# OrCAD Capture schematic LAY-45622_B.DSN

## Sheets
1 PAGE1: size A3; title: DK6 V3; rev: 1; note: CARRIER BOARD
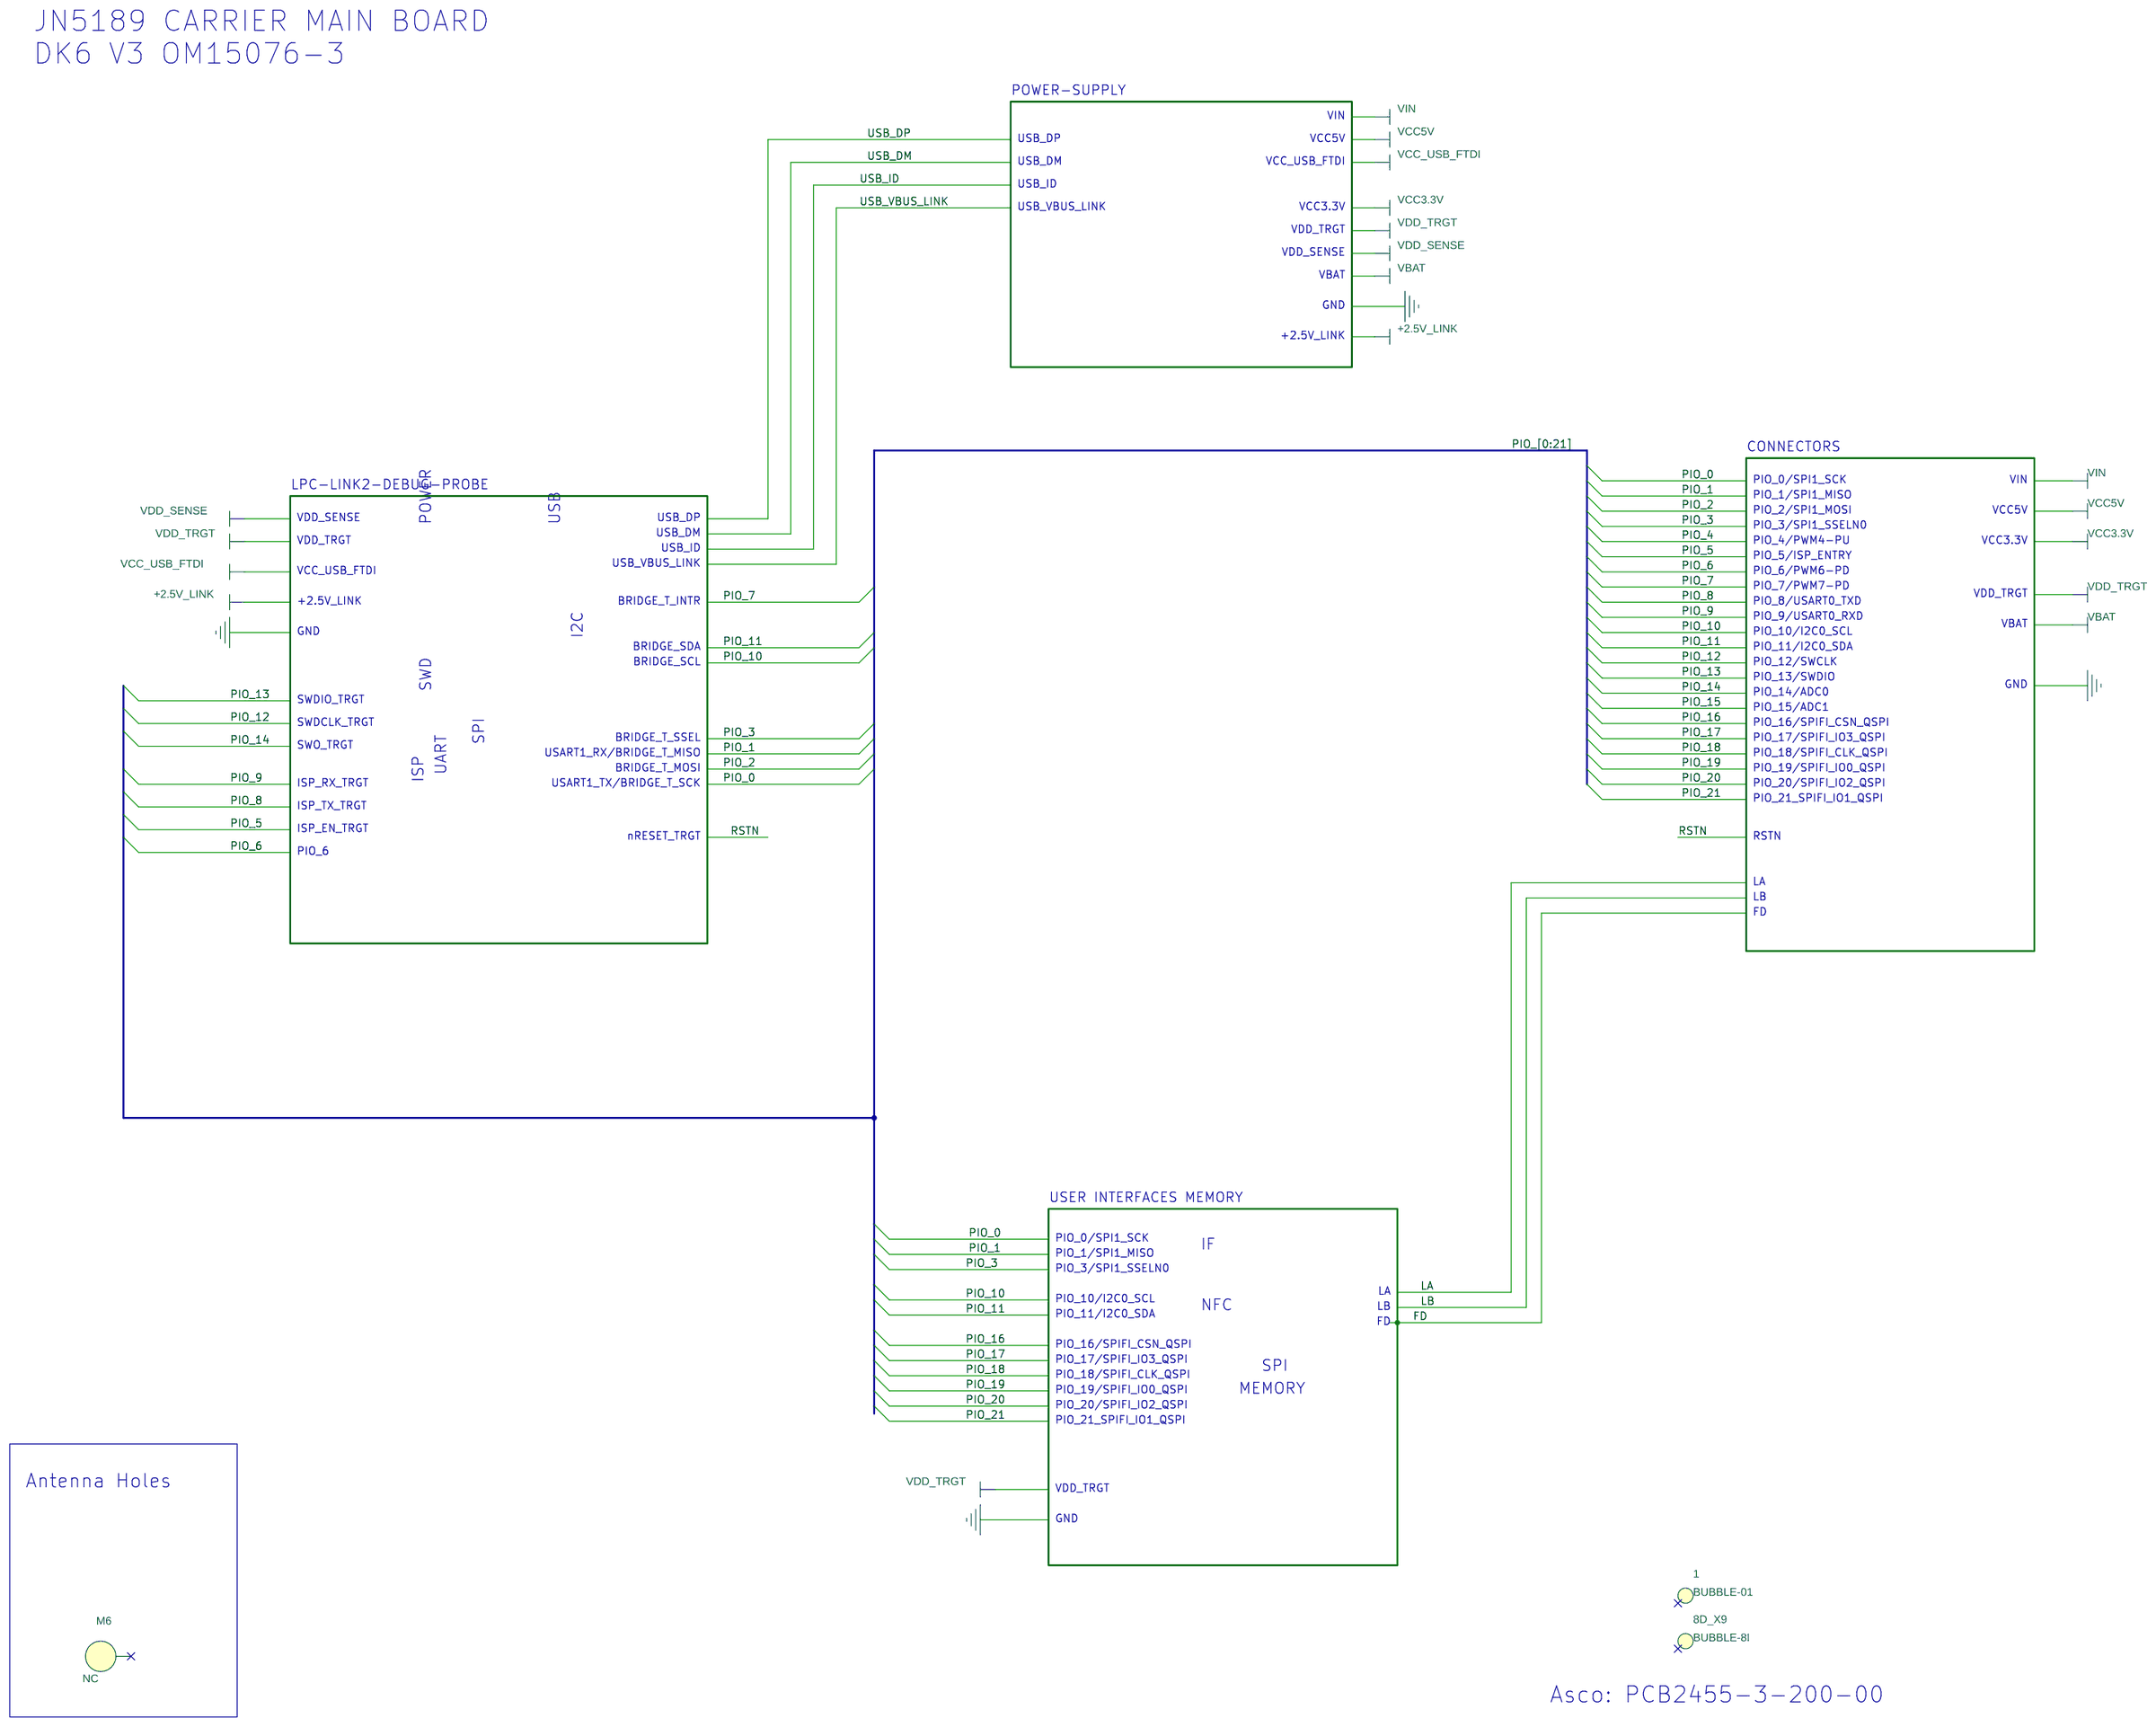
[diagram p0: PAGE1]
2 PAGE1 (2): size A3; title: LPC-LINK2-DEBUG-PROBE 1/3; block LPC-LINK2-DEBUG-PROBE
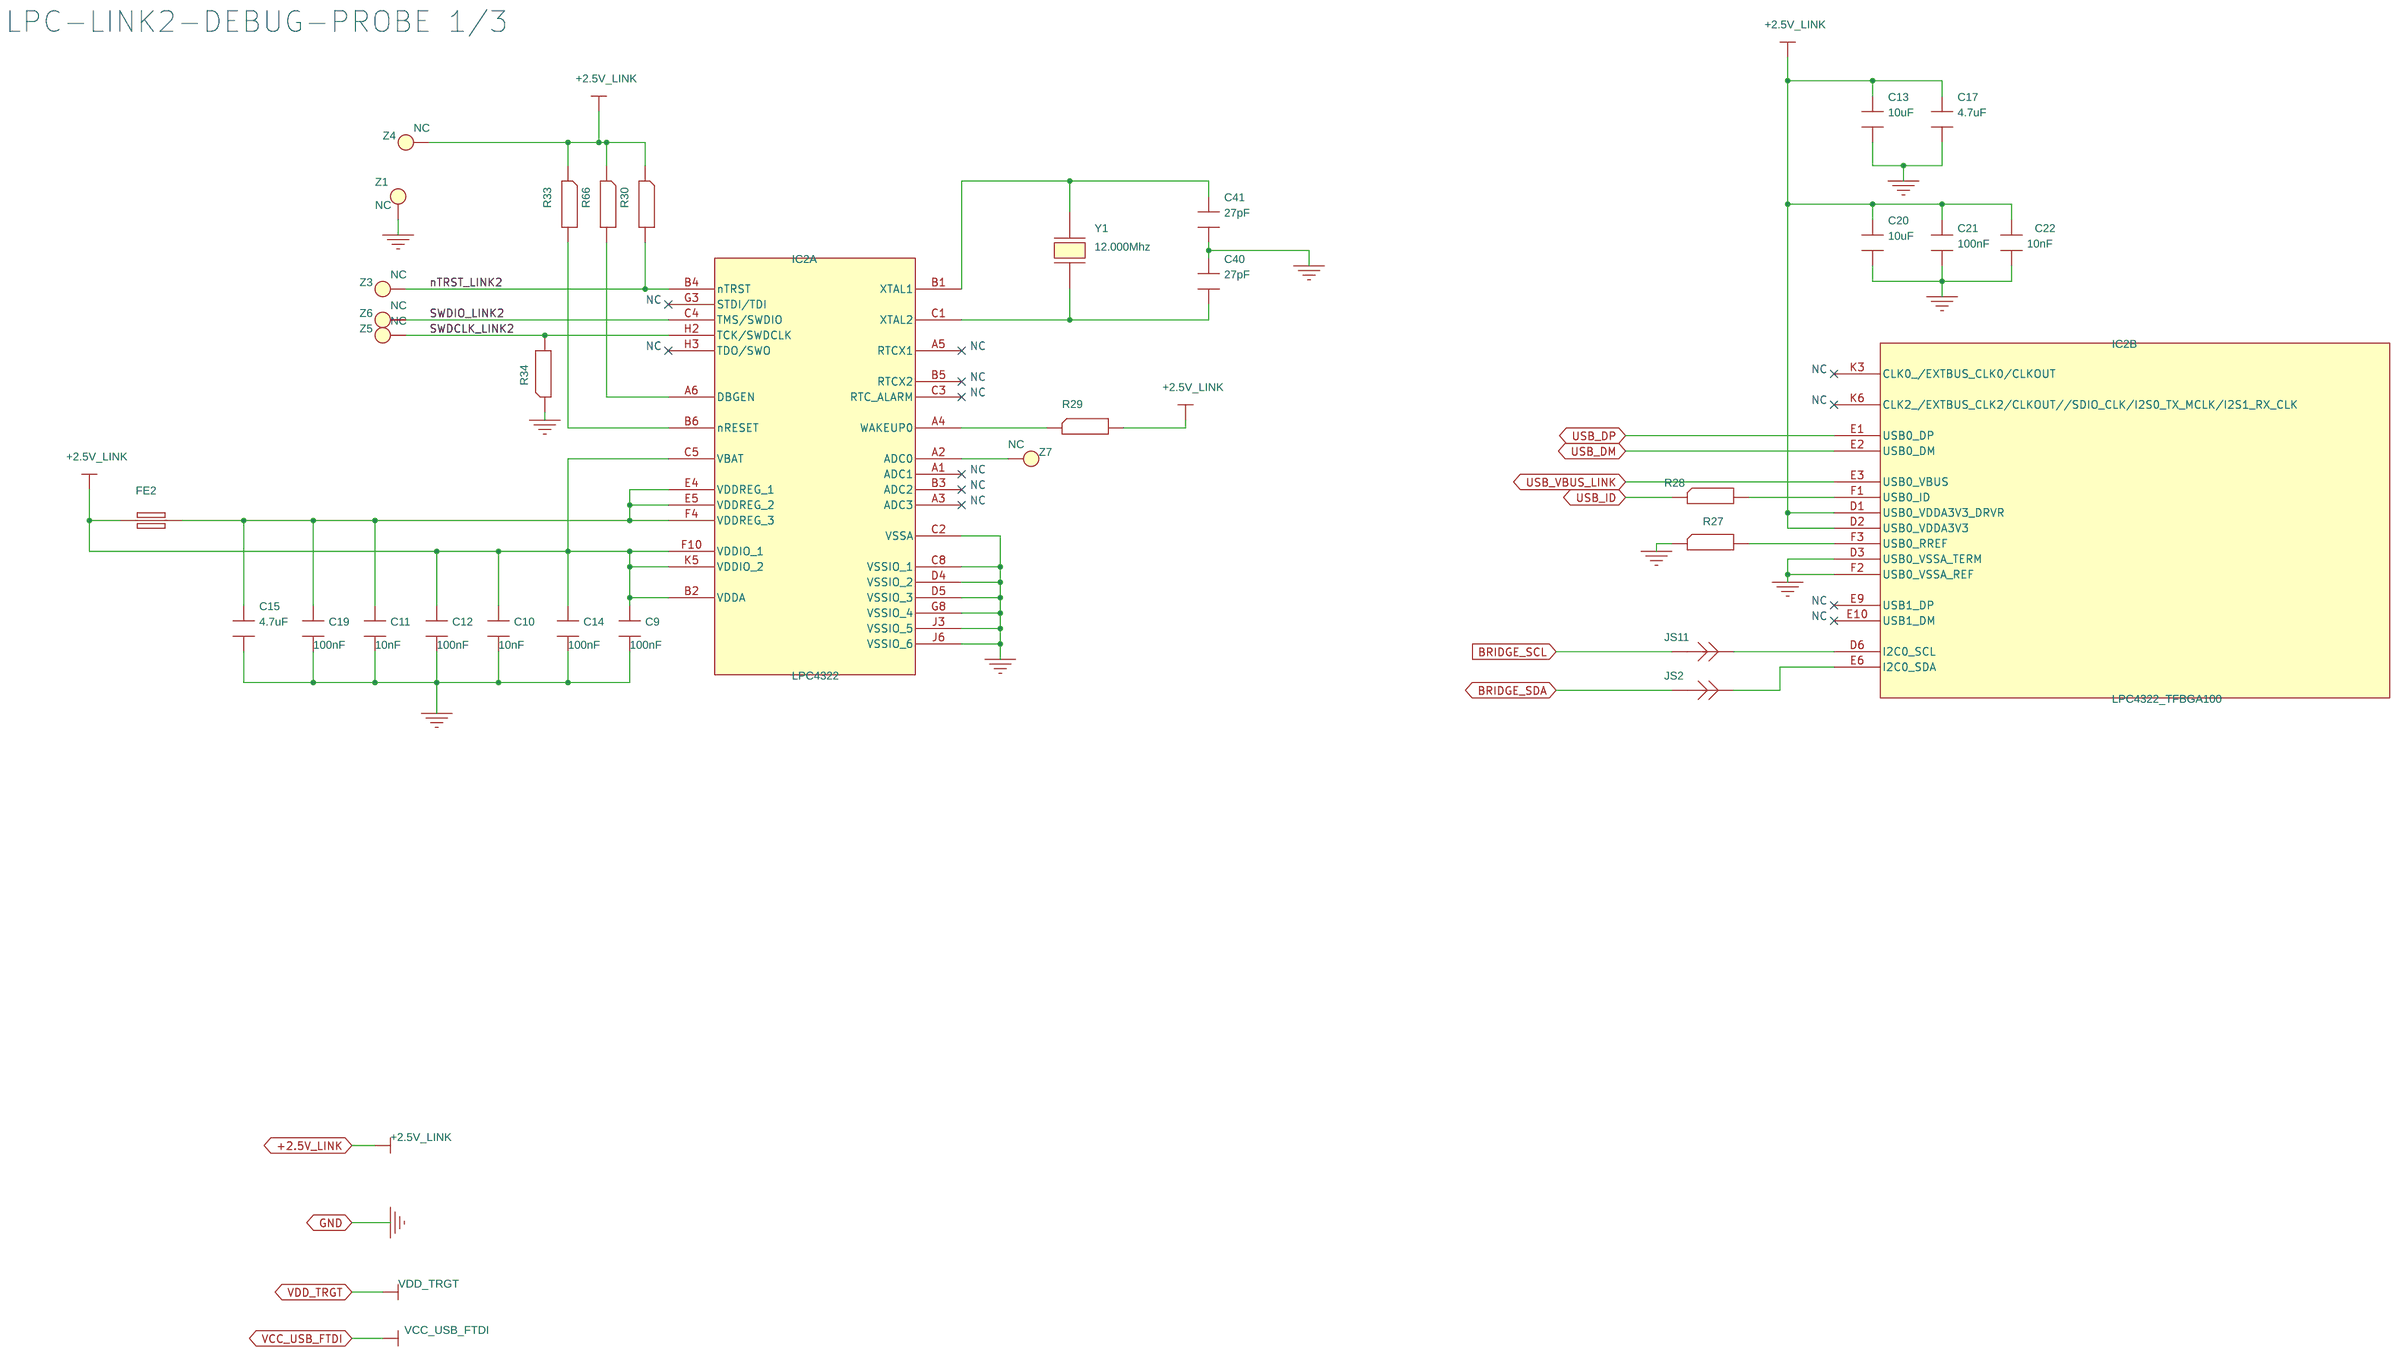
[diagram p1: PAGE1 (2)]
3 PAGE2: size A3; title: LPC-LINK2-DEBUG-PROBE 2/3; block LPC-LINK2-DEBUG-PROBE
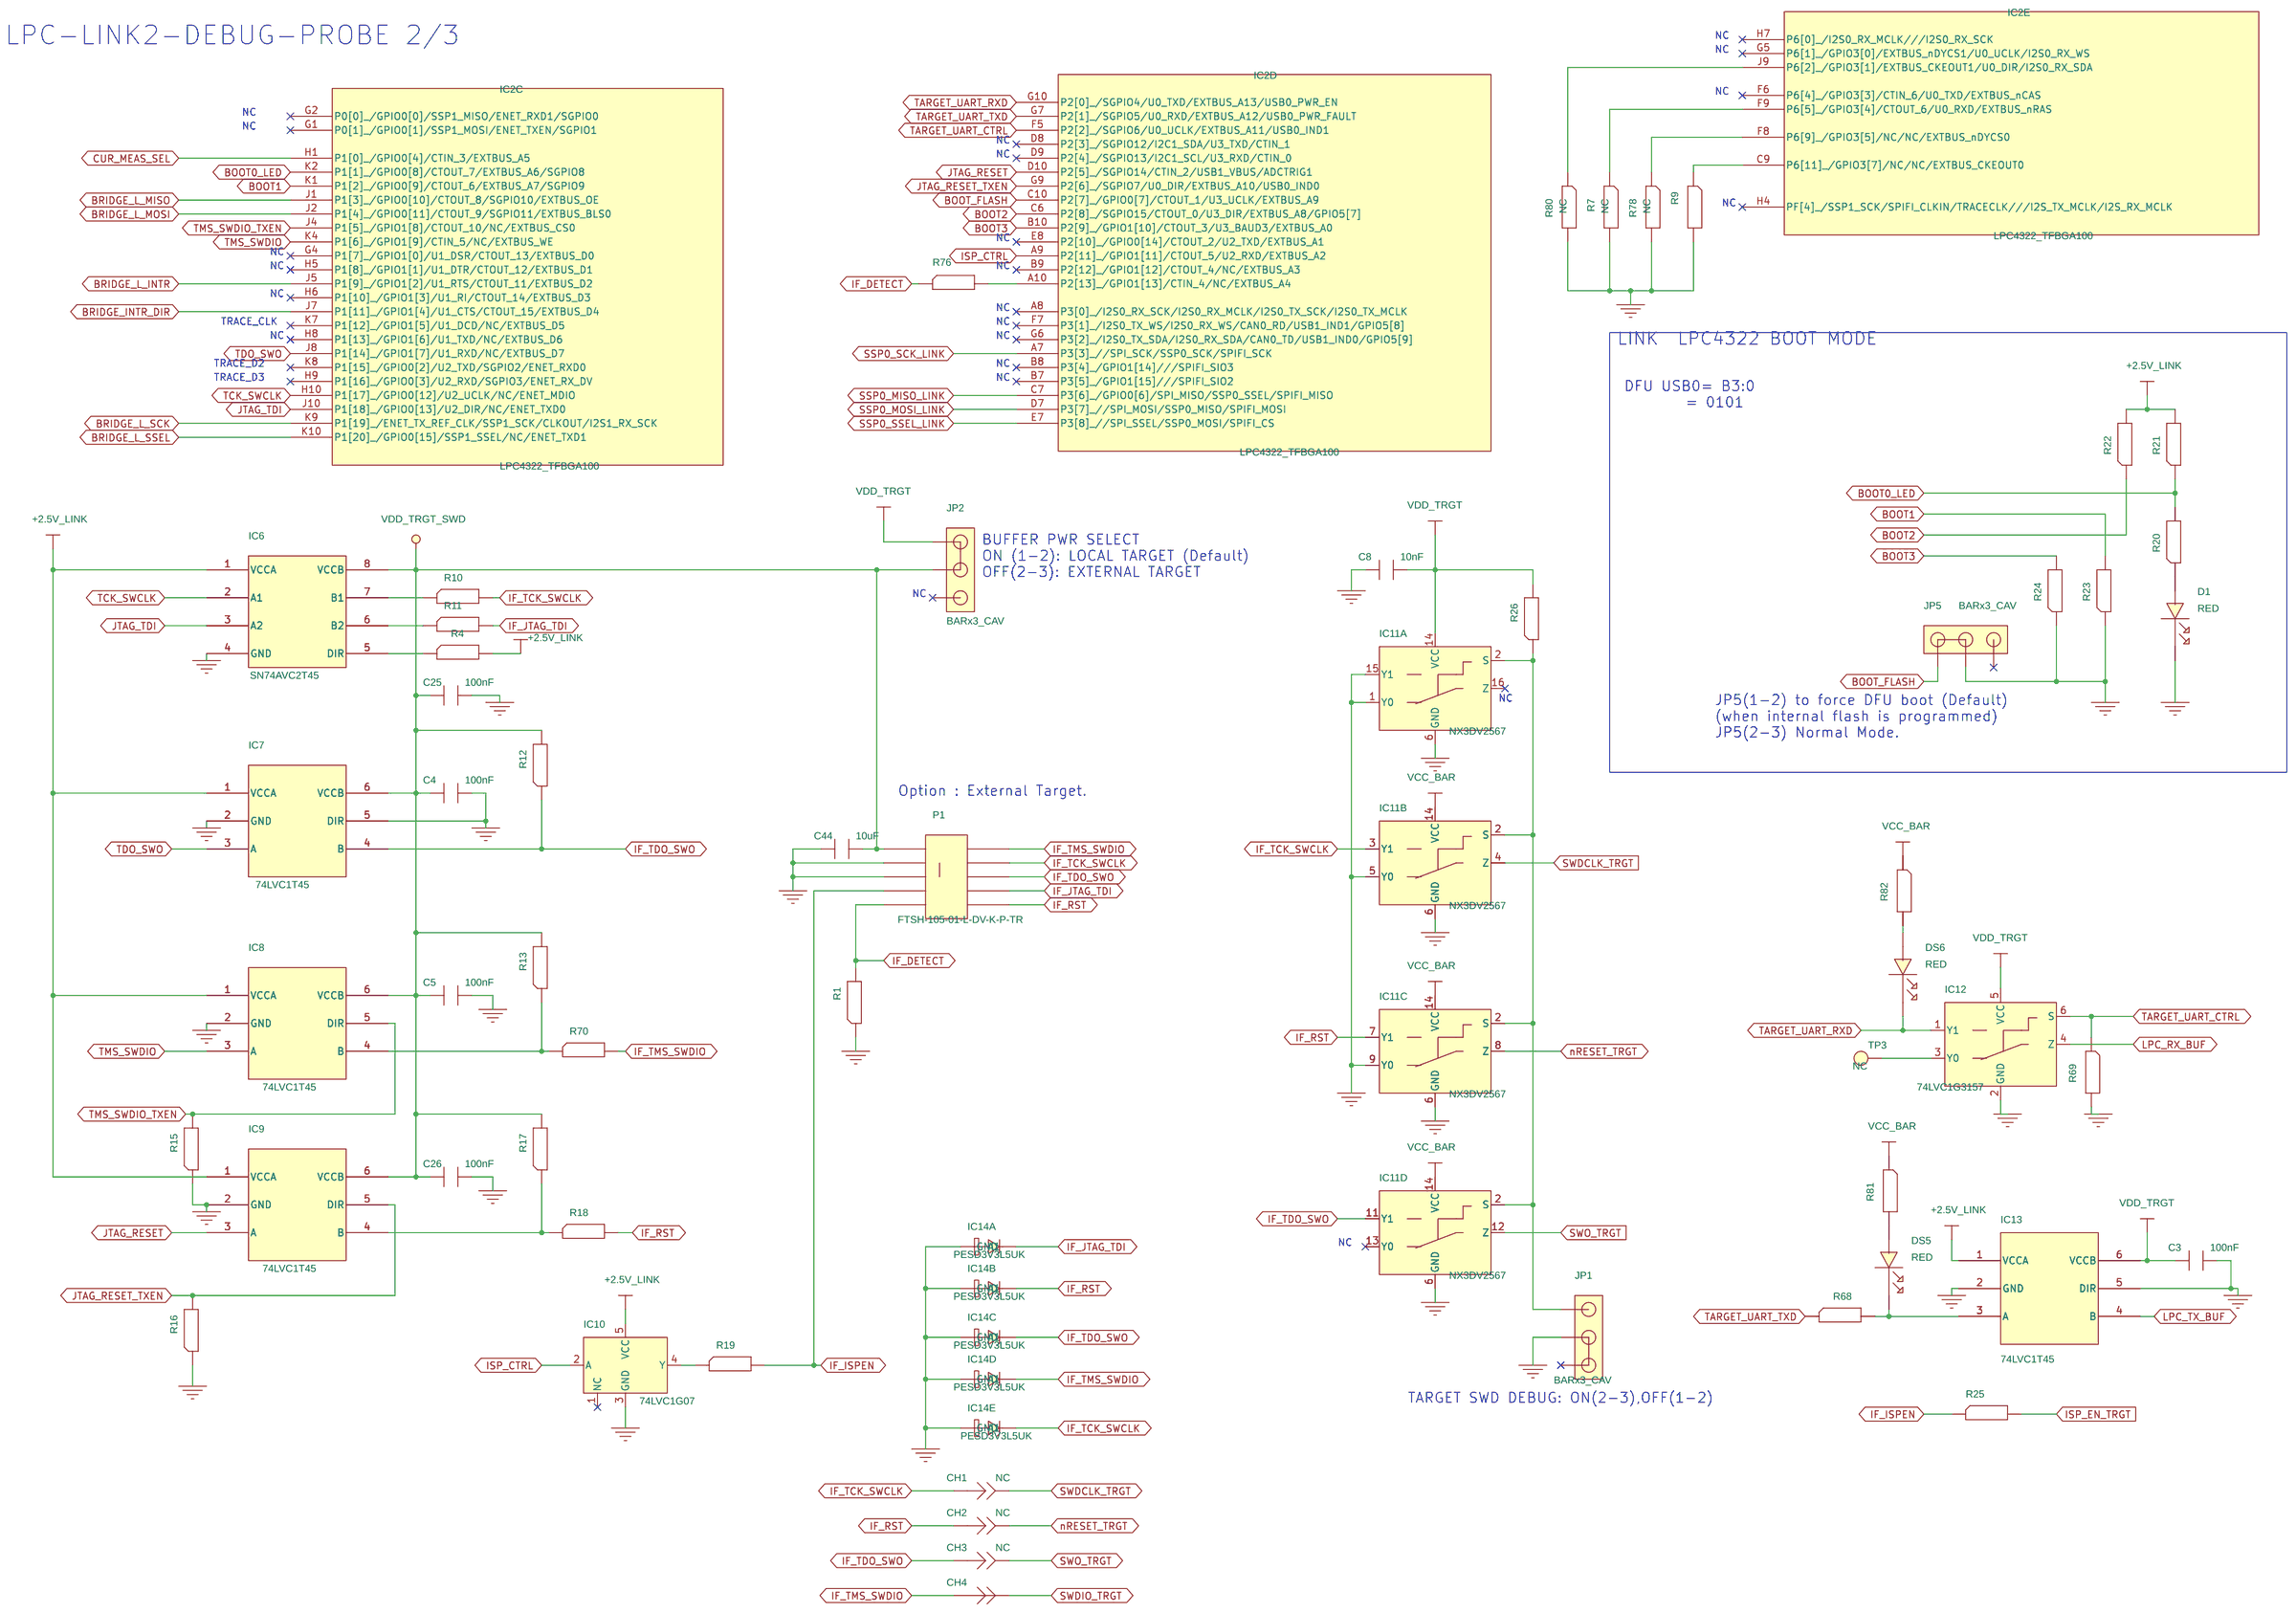
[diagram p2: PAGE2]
4 PAGE3: size A3; title: LPC-LINK2-DEBUG-PROBE 3/3; block LPC-LINK2-DEBUG-PROBE
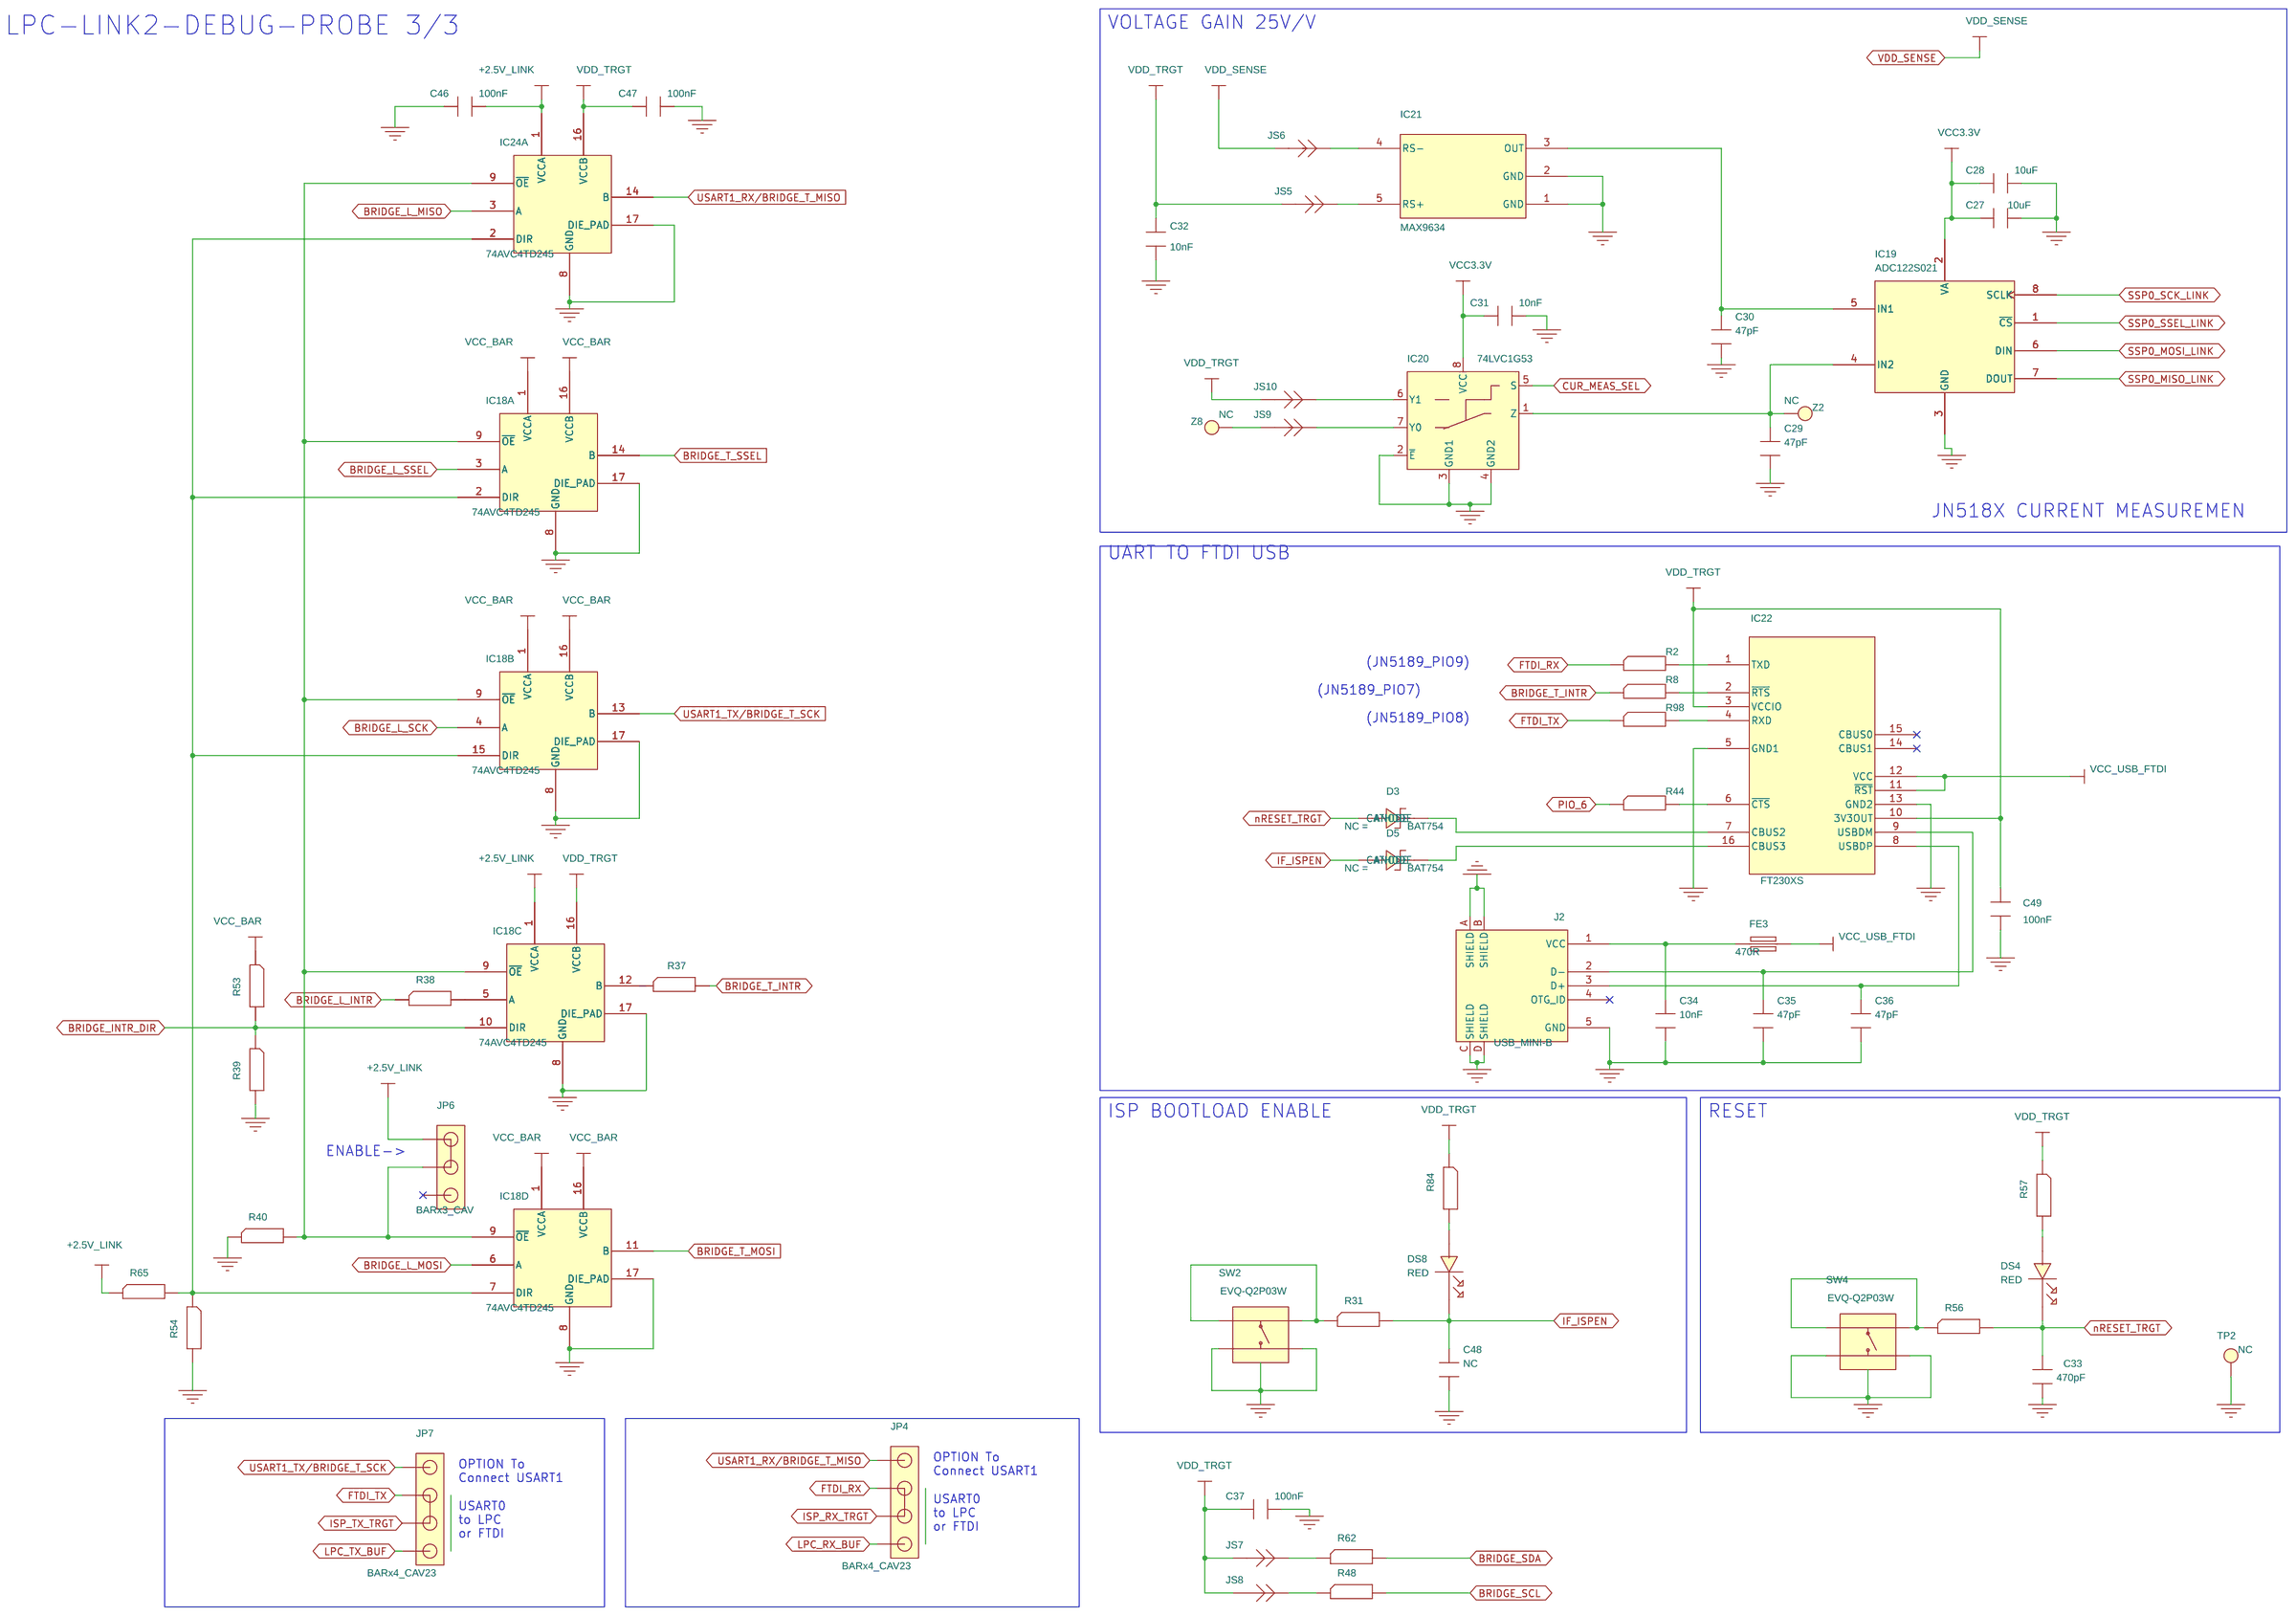
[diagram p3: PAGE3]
5 ALIM: size A3; title: POWER SUPPLY; block POWER-SUPPLY
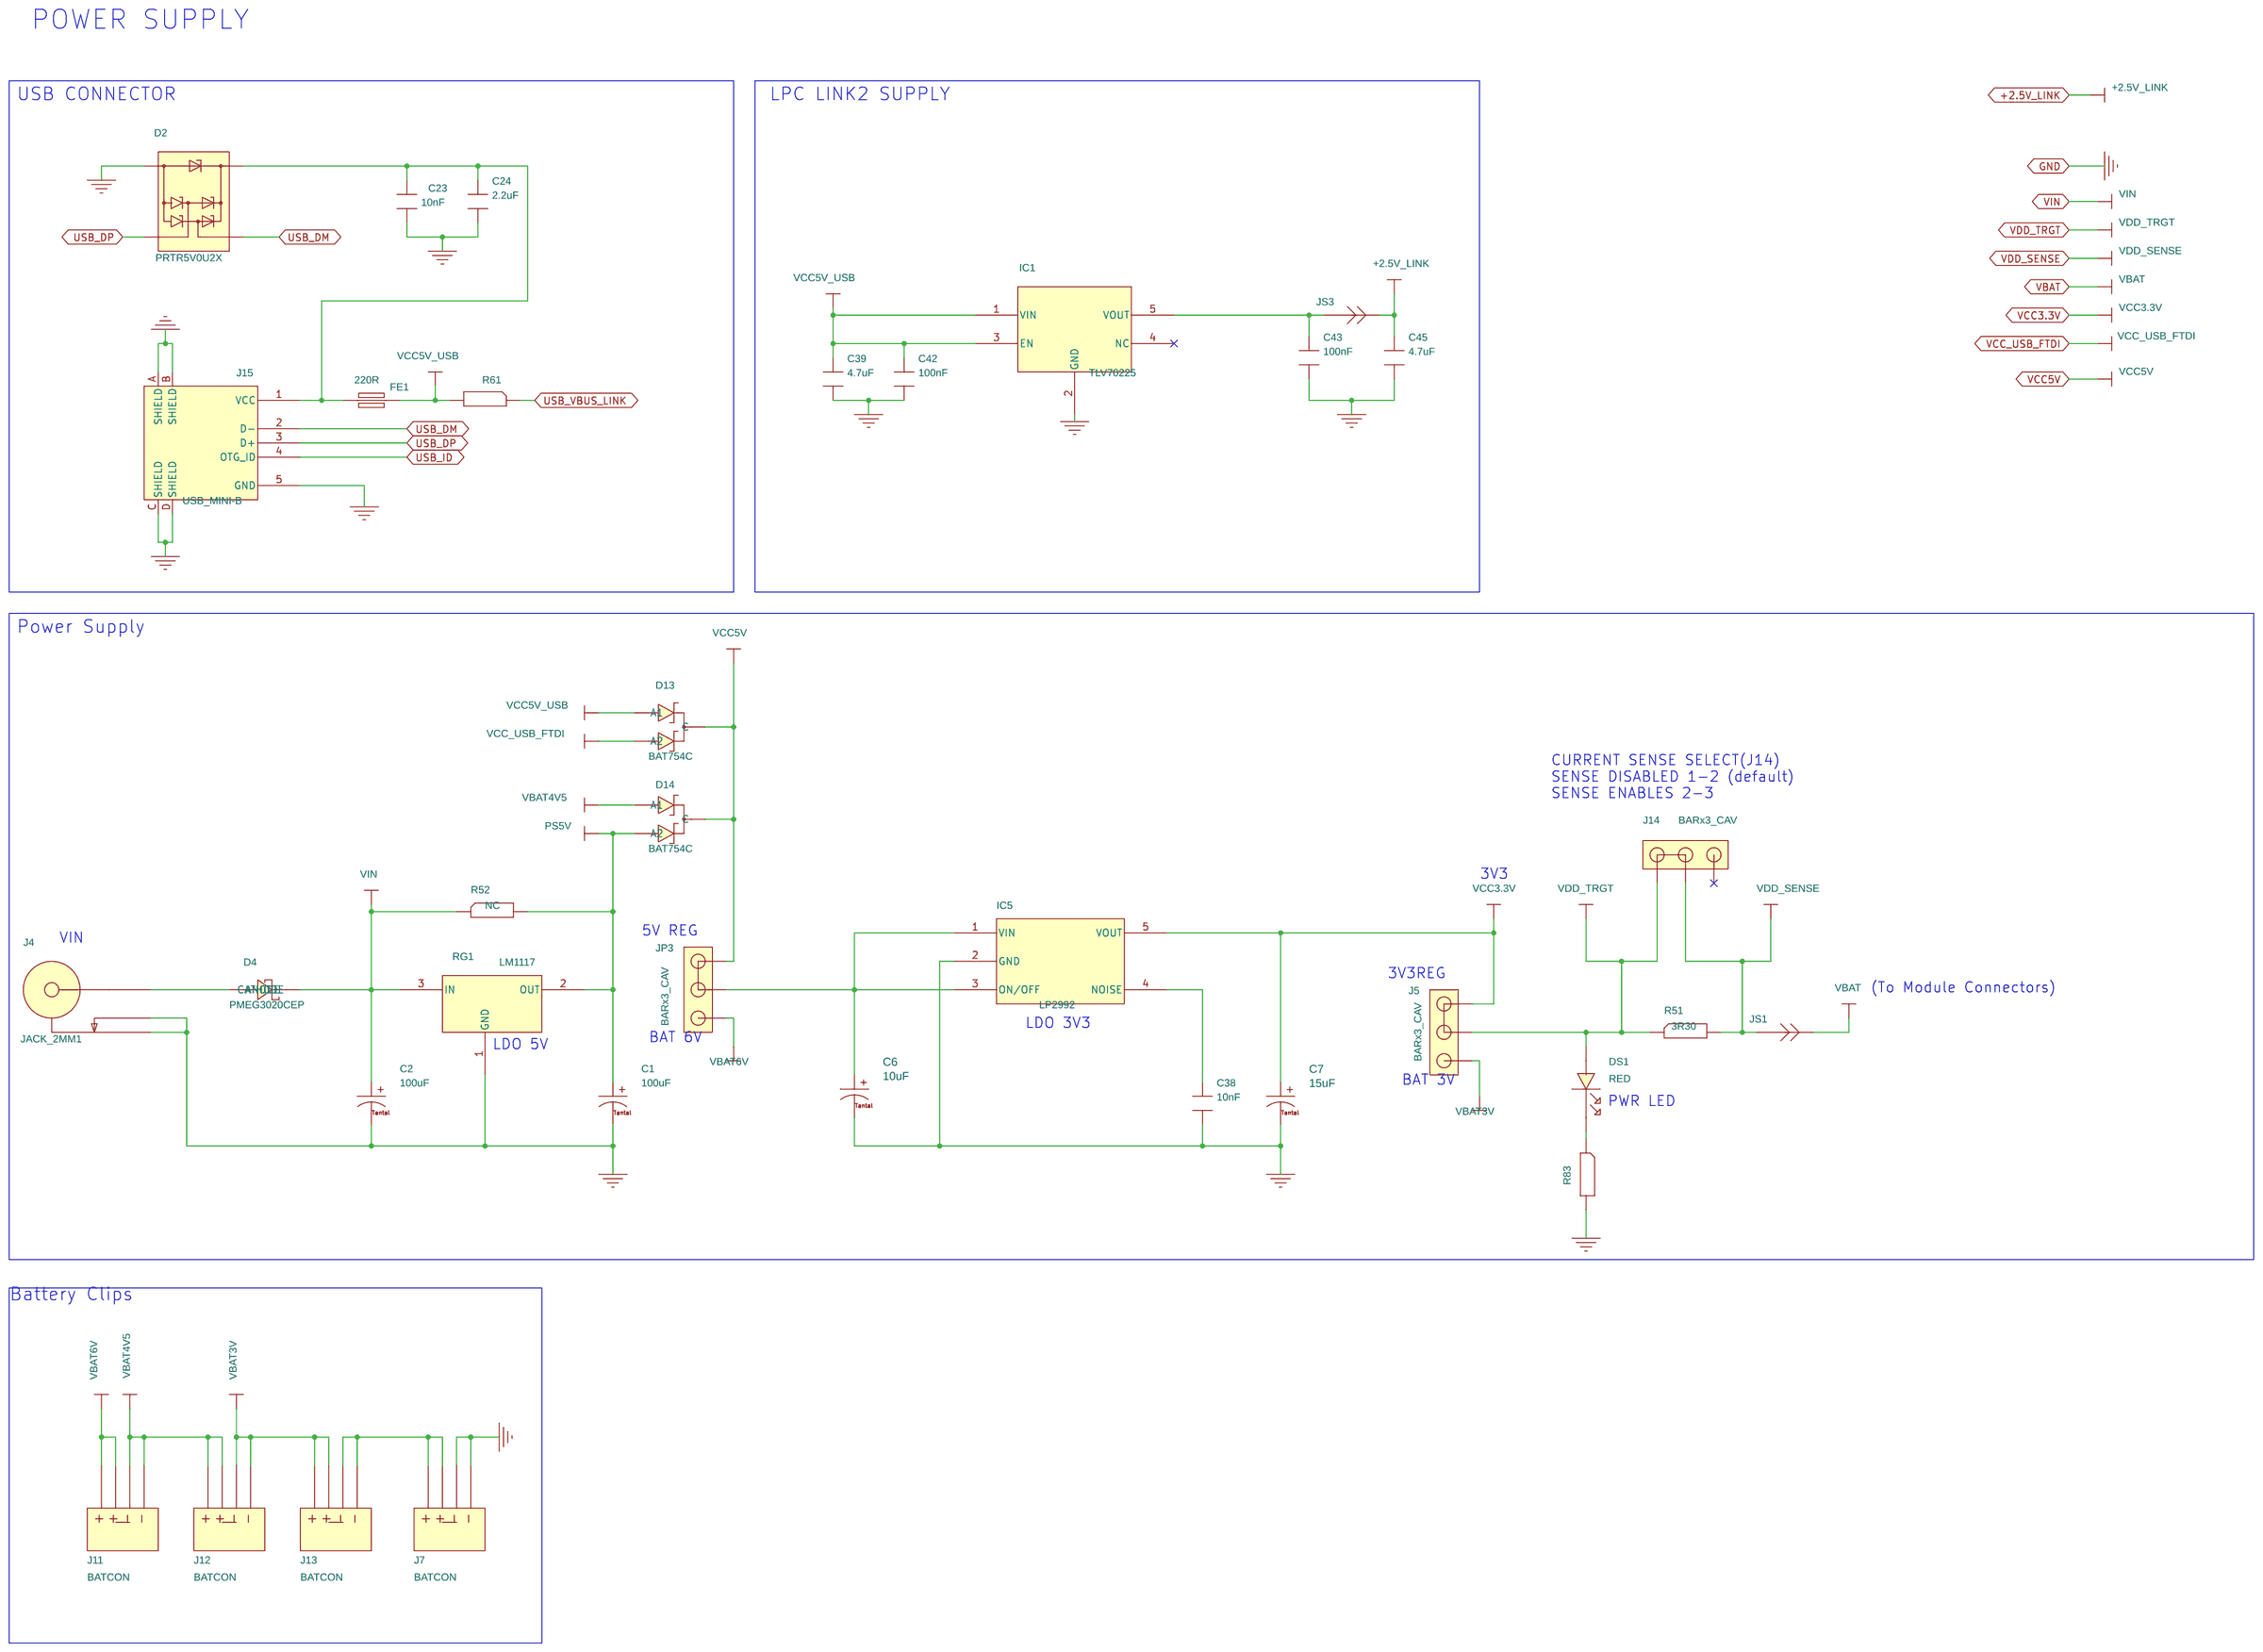
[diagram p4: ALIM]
6 PAGE1 (3): size A3; title: USER INTERFACES MEMORY; block USER INTERFACES MEMORY
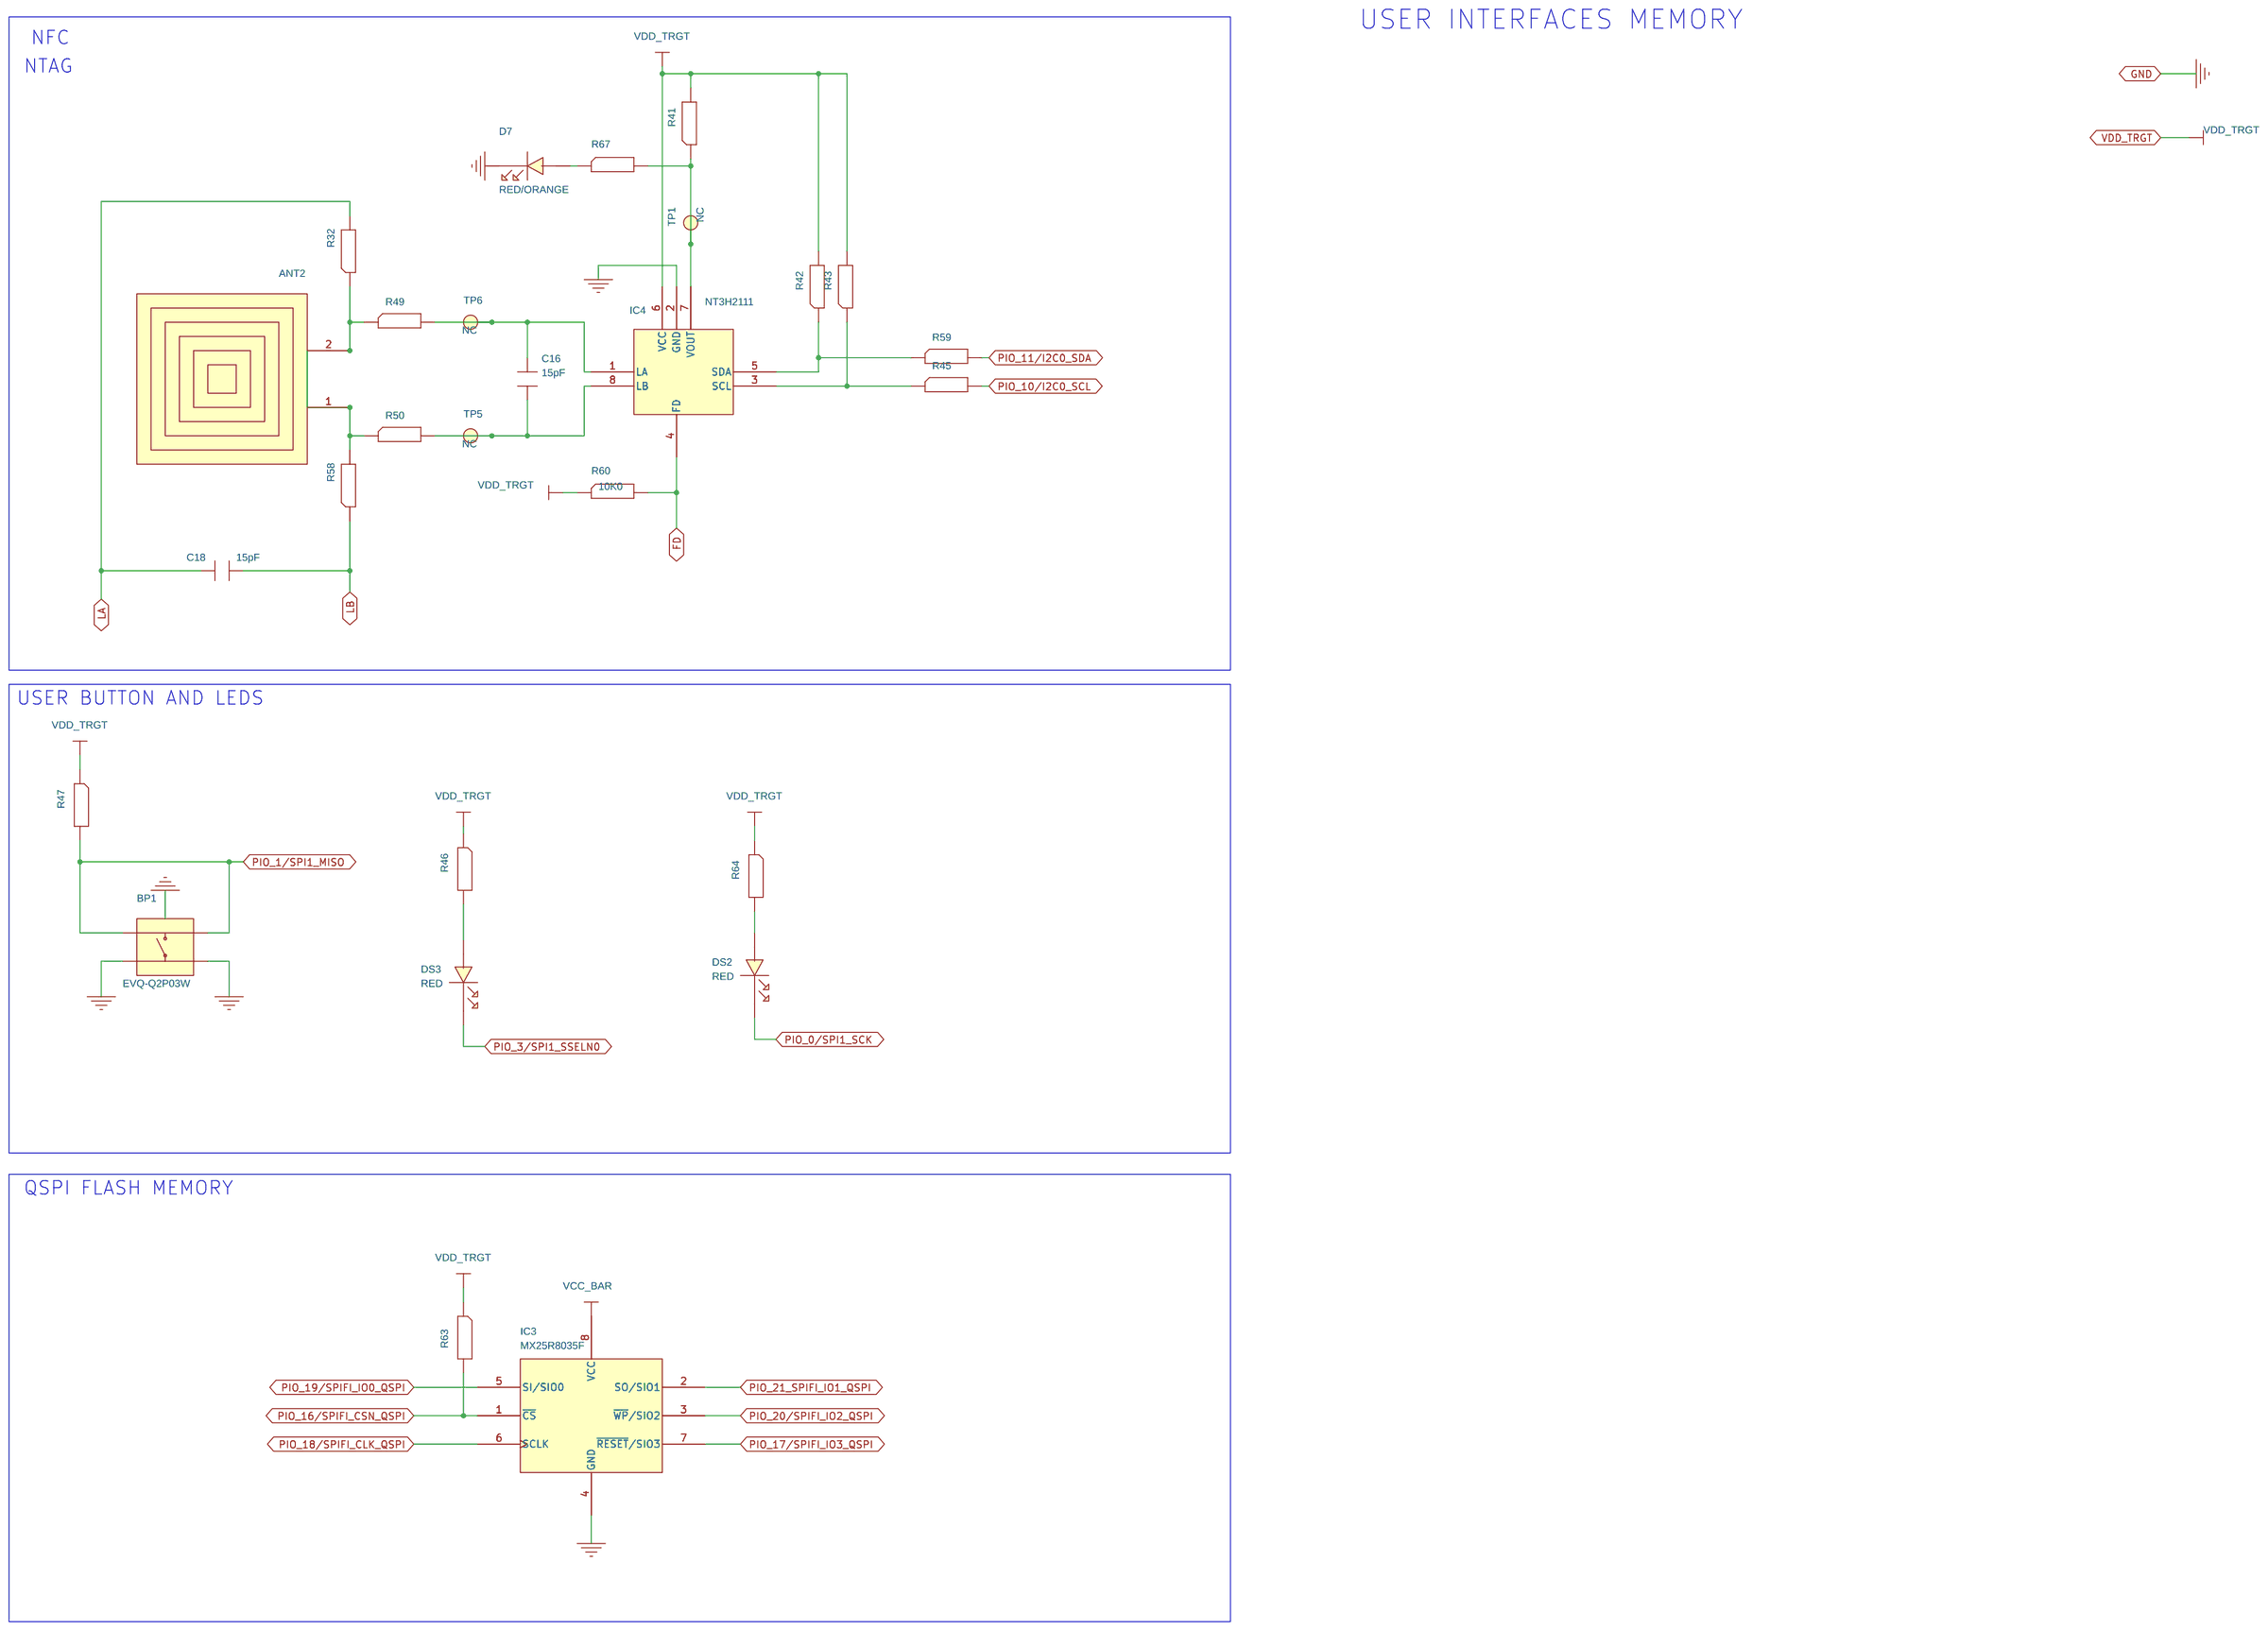
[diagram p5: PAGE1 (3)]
7 PAGE1 (4): size A3; title: CONNECTORS; block CONNECTORS
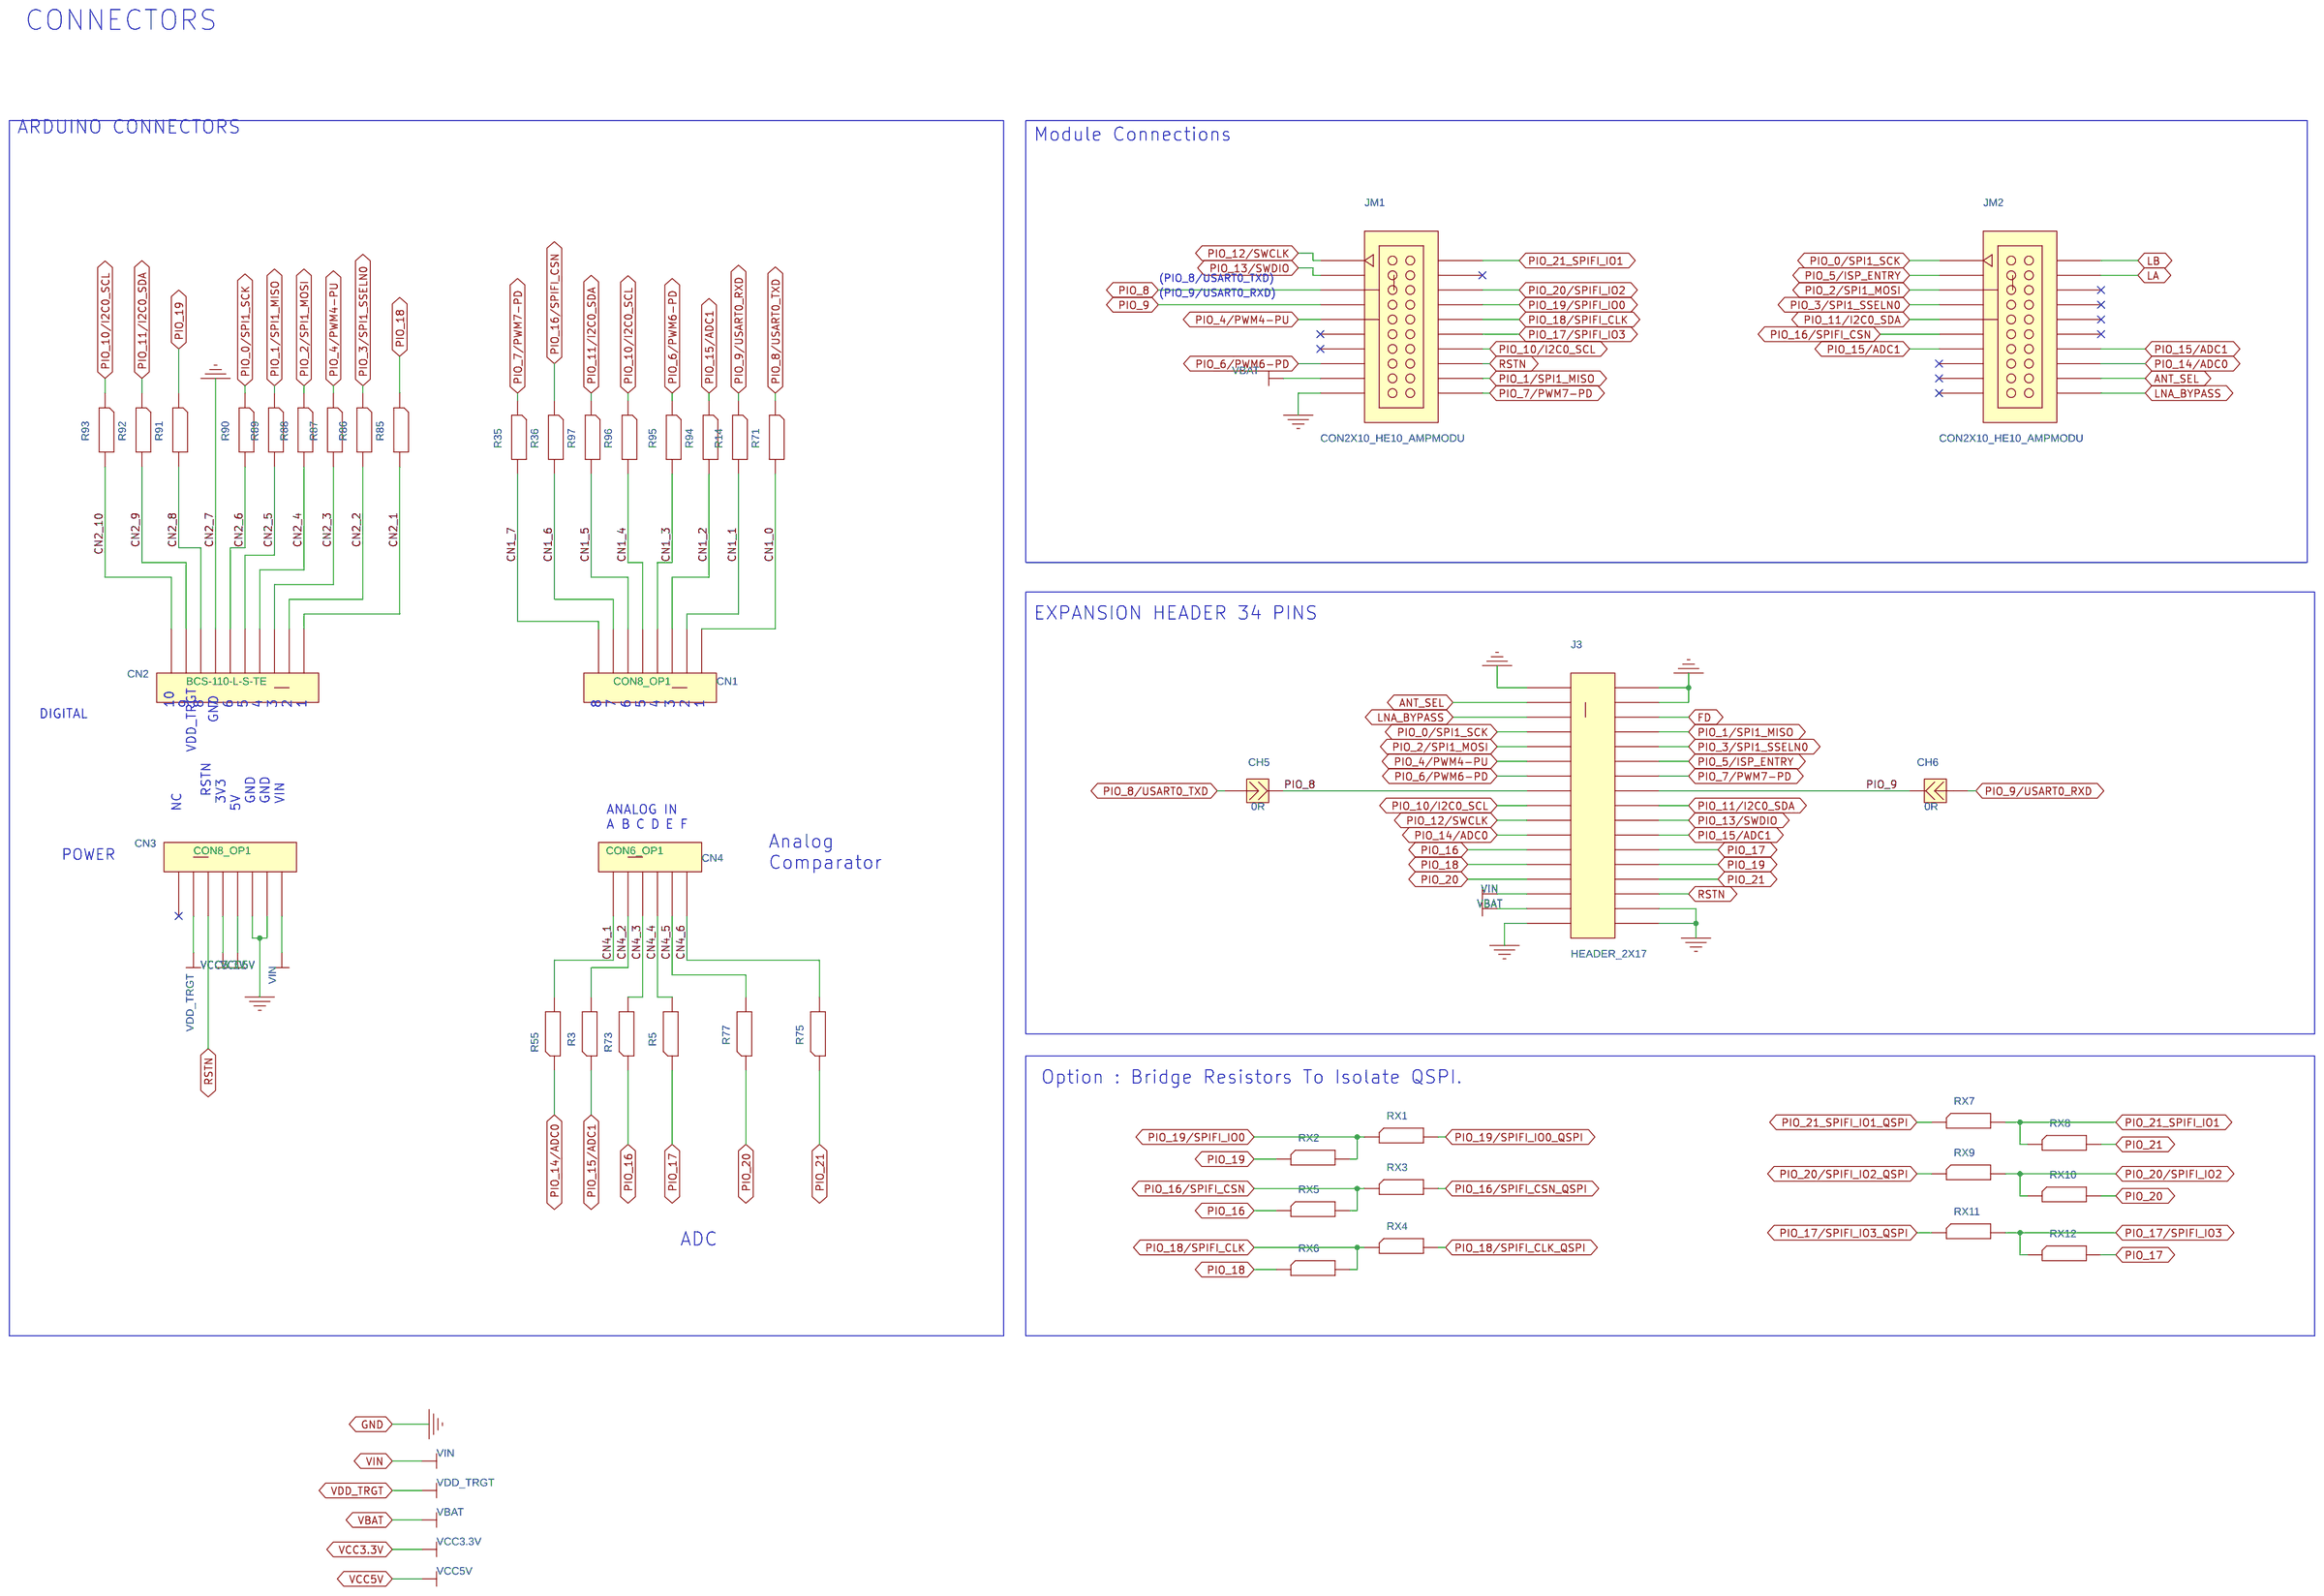
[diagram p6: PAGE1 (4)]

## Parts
sheet ALIM
C1  100uF  [7343-43_ipcb]
C2  100uF  [7343-43_ipcb]
C6  10uF  [TAJ_A]
C7  15uF  [TAJ_A]
C23  10nF  [C0402]
C24  2.2uF  [C0402]
C38  10nF  [C0402]
C39  4.7uF  [C0402]
C42  100nF  [C0402]
C43  100nF  [C0402]
C45  4.7uF  [C0402]
D2  PRTR5V0U2X  [SOT143B]
D4  PMEG3020CEP  [SOD128_A1_K2]
D13  BAT754C  [SOT23]
D14  BAT754C  [SOT23]
DS1  RED  [LED_0603_A_K]
FE1  220R  [blm18]
IC1  TLV70225  [SOT23_5_095]
IC5  LP2992  [SOT23_5_095]
J4  JACK_2MM1  [jack2_1_smt]
J5  BARx3_CAV  [bar_3pts_2mm00_cav12]
J7  BATCON  [BATCON_SMD_2CLIPS_AAA]
J11  BATCON  [BATCON_SMD_2CLIPS_AAA]
J12  BATCON  [BATCON_SMD_2CLIPS_AAA]
J13  BATCON  [BATCON_SMD_2CLIPS_AAA]
J14  BARx3_CAV  [bar_3pts_2mm00_cav12]
J15  USB_MINI-B  [usb_mini-b]
JP3  BARx3_CAV  [bar_3pts_2mm00_cav12]
JS1  NC  [CHEVRON_0603_F_COPPER]
JS3  NC  [CHEVRON_0603_F_COPPER]
R51  3R30  [R0402]
R52  NC  [R0402]
R61  270R  [R0402]
R83  680R  [R0402]
RG1  LM1117  [DPAK4_APPS]
sheet PAGE1 (2)
C9  100nF  [C0402]
C10  10nF  [C0402]
C11  10nF  [C0402]
C12  100nF  [C0402]
C13  10uF  [C0402]
C14  100nF  [C0402]
C15  4.7uF  [C0402]
C17  4.7uF  [C0402]
C19  100nF  [C0402]
C20  10uF  [C0402]
C21  100nF  [C0402]
C22  10nF  [C0402]
C40  27pF  [C0402]
C41  27pF  [C0402]
FE2  470R  [blm18]
IC2  LPC4322  [BGA100_080_SQ9]  (sections A,B,C,D,E)
JS2  NC  [CHEVRON_0603_F_COPPER]
JS11  NC  [CHEVRON_0603_F_COPPER]
R27  12K0  [R0402]
R28  0R  [R0402]
R29  100K  [R0402]
R30  12K0  [R0402]
R33  12K0  [R0402]
R34  2K20  [R0402]
R66  12K0  [R0402]
Y1  12.000Mhz  [HC49US_AT49]
Z1  NC  [VIA_0MM9]
Z3  NC  [VIA_0MM9]
Z4  NC  [VIA_0MM9]
Z5  NC  [VIA_0MM9]
Z6  NC  [VIA_0MM9]
Z7  NC  [VIA_0MM9]
sheet PAGE1 (3)
ANT2  NC  [ANT_6T_40MM5x24MM5]
BP1  EVQ-Q2P03W  [BP_EVQQ2]
C16  15pF  [C0402]
C18  15pF  [C0402]
D7  RED/ORANGE  [LED_0603_A_K]
DS2  RED  [LED_0603_A_K]
DS3  RED  [LED_0603_A_K]
IC3  MX25R8035F  [SOP8_127_200]
IC4  NT3H2111  [sot902-3]
R32  0R  [R0402]
R41  NC  [R0402]
R42  4K7  [R0402]
R43  4K7  [R0402]
R45  NC  [R0402]
R46  2K20  [R0402]
R47  2K20  [R0402]
R49  NC  [R0402]
R50  NC  [R0402]
R58  0R  [R0402]
R59  NC  [R0402]
R60  10K0  [R0402]
R63  100K  [R0402]
R64  2K20  [R0402]
R67  680R  [R0402]
TP1  NC  [plot050]
TP5  NC  [plot050]
TP6  NC  [plot050]
sheet PAGE1 (4)
CH5  0R  [CHEVRON_0603_F]
CH6  0R  [CHEVRON_0603_F]
CN1  CON8_OP1  [SIP-8P]
CN2  BCS-110-L-S-TE  [SIP-10P]
CN3  CON8_OP1  [SIP-8P]
CN4  CON6_OP1  [SIP-6P]
J3  HEADER_2X17  [header34_2x17_254]
JM1  CON2X10_HE10_AMPMODU  [AMPMODU_REC20_NOHOLES]
JM2  CON2X10_HE10_AMPMODU  [AMPMODU_REC20_NOHOLES]
R3  0R  [R0402]
R5  0R  [R0402]
R14  0R  [R0402]
R35  0R  [R0402]
R36  0R  [R0402]
R55  0R  [R0402]
R71  0R  [R0402]
R73  0R  [R0402]
R75  0R  [R0402]
R77  0R  [R0402]
R85  0R  [R0402]
R86  0R  [R0402]
R87  0R  [R0402]
R88  0R  [R0402]
R89  0R  [R0402]
R90  0R  [R0402]
R91  0R  [R0402]
R92  0R  [R0402]
R93  0R  [R0402]
R94  0R  [R0402]
R95  0R  [R0402]
R96  0R  [R0402]
R97  0R  [R0402]
RX1  0R  [R0402]
RX2  0R  [R0402]
RX3  0R  [R0402]
RX4  0R  [R0402]
RX5  0R  [R0402]
RX6  0R  [R0402]
RX7  0R  [R0402]
RX8  0R  [R0402]
RX9  0R  [R0402]
RX10  0R  [R0402]
RX11  0R  [R0402]
RX12  0R  [R0402]
sheet PAGE1
1  BUBBLE-01  [BUBBLE_DIAM8]
8D_X9  BUBBLE-8I  [BUBBLE_DIAM8]
M6  NC  [tp2-ha_apps_zi16]
sheet PAGE2
C3  100nF  [C0402]
C4  100nF  [C0402]
C5  100nF  [C0402]
C8  10nF  [C0402]
C25  100nF  [C0402]
C26  100nF  [C0402]
C44  10uF  [C0402]
CH1  NC  [CHEVRON_0603_O]
CH2  NC  [CHEVRON_0603_O]
CH3  NC  [CHEVRON_0603_O]
CH4  NC  [CHEVRON_0603_F_COPPER]
D1  RED  [LED_0603_A_K]
DS5  RED  [LED_0603_A_K]
DS6  RED  [LED_0603_A_K]
IC6  SN74AVC2T45  [MSOP8_065L]
IC7  74LVC1T45  [SOT-363_SC-88]
IC8  74LVC1T45  [SOT-363_SC-88]
IC9  74LVC1T45  [SOT-363_SC-88]
IC10  74LVC1G07  [SOT353_065]
IC11  NX3DV2567  [SOT1161-1_XQFN16]  (sections A,B,C,D)
IC12  74LVC1G3157  [SOT-363_SC-88]
IC13  74LVC1T45  [SOT-363_SC-88]
IC14  PESD3V3L5UK  [SOT891_XSON6]  (sections A,B,C,D,E)
JP1  BARx3_CAV  [bar_3pts_2mm00_cav23]
JP2  BARx3_CAV  [bar_3pts_2mm00_cav12]
JP5  BARx3_CAV  [bar_3pts_2mm00_cav12]
P1  FTSH-105-01-L-DV-K-P-TR  [CON_SAMTEC_FTSH_105_01_L_DV_K]
R1  0R  [R0402]
R4  100K  [R0402]
R7  NC  [R0402]
R9  2K20  [R0402]
R10  100R  [R0402]
R11  100R  [R0402]
R12  100K  [R0402]
R13  100K  [R0402]
R15  2K20  [R0402]
R16  2K20  [R0402]
R17  100K  [R0402]
R18  100R  [R0402]
R19  100R  [R0402]
R20  2K20  [R0402]
R21  2K20  [R0402]
R22  2K20  [R0402]
R23  2K20  [R0402]
R24  2K20  [R0402]
R25  0R  [R0402]
R26  100K  [R0402]
R68  100R  [R0402]
R69  2K20  [R0402]
R70  100R  [R0402]
R76  1K50  [R0402]
R78  NC  [R0402]
R80  NC  [R0402]
R81  680R  [R0402]
R82  680R  [R0402]
TP3  NC  [plot050]
sheet PAGE3
C27  10uF  [C0402]
C28  10uF  [C0402]
C29  47pF  [C0402]
C30  47pF  [C0402]
C31  10nF  [C0402]
C32  10nF  [C0402]
C33  470pF  [C0402]
C34  10nF  [C0402]
C35  47pF  [C0402]
C36  47pF  [C0402]
C37  100nF  [C0402]
C46  100nF  [C0402]
C47  100nF  [C0402]
C48  NC  [C0402]
C49  100nF  [C0402]
D3  BAT754  [SOT23]
D5  BAT754  [SOT23]
DS4  RED  [LED_0603_A_K]
DS8  RED  [LED_0603_A_K]
FE3  470R  [blm18]
IC18  74AVC4TD245  [SOT763-1_DHVQFN20_050]  (sections A,B,C,D)
IC19  ADC122S021  [MSOP8_065L]
IC20  74LVC1G53  [SOT765-1_VSSOP8]
IC21  MAX9634  [SOT23_5_095]
IC22  FT230XS  [jedec_mo137_ab_ssop16]
IC24  74AVC4TD245  [SOT763-1_DHVQFN20_050]  (section A)
J2  USB_MINI-B  [usb_mini-b]
JP4  BARx4_CAV23  [bar_4pts_2mm00_cav23]
JP6  BARx3_CAV  [bar_3pts_2mm00_cav12]
JP7  BARx4_CAV23  [bar_4pts_2mm00_cav23]
JS5  NC  [CHEVRON_0603_F_COPPER]
JS6  NC  [CHEVRON_0603_F_COPPER]
JS7  NC  [CHEVRON_0603_F_COPPER]
JS8  NC  [CHEVRON_0603_F_COPPER]
JS9  NC  [CHEVRON_0603_F_COPPER]
JS10  NC  [CHEVRON_0603_F_COPPER]
R2  0R  [R0402]
R8  NC  [R0402]
R31  0R  [R0402]
R37  2K20  [R0402]
R38  2K20  [R0402]
R39  2K20  [R0402]
R40  2K20  [R0402]
R44  NC  [R0402]
R48  4K7  [R0402]
R53  NC  [R0402]
R54  NC  [R0402]
R56  0R  [R0402]
R57  2K20  [R0402]
R62  4K7  [R0402]
R65  100K  [R0402]
R84  2K20  [R0402]
R98  0R  [R0402]
SW2  EVQ-Q2P03W  [BP_EVQQ2]
SW4  EVQ-Q2P03W  [BP_EVQQ2]
TP2  NC  [plot10]
Z2  NC  [VIA_0MM9]
Z8  NC  [VIA_0MM9]

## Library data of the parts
C1 C2 = CAPA_TANTALE: Designation: Capacitor T521 100uF 20% 25V (Boitier X (7343-43)); MANUFACTURER_REFERENCE: KEMET (T521X107M025ATE060); Package: 7343-43; Part Number: 0-00-305210A; Part Type: Capacitor; Tension: 25V; Tol: 20%
C6 = CAPA_TANTALE: Designation: Capacitor TAJ 10uF 10% 10V (boitier_A); MANUFACTURER_REFERENCE: KEMET (T491A106K010AT); Package: TAJ_boitier_A; Part Number: 0-00-301422B; Part Type: Capacitor; Supplier: FARNELL; Tension: 10V; Tol: 10%
C7 = CAPA_TANTALE: Designation: Capacitor Tantal 15uF 20% 6.3V (Boitier A); Package: 3216-18; Part Number: 0-00-300746; Part Type: Capacitor; Tension: 6.3V; Tol: 20%
C8 C10 C11 C22 C23 C31 C32 C38 = CAPA: Alt_Symbols: 0402C; Designation: Capacitor 0402 10nF 10% 16V X7R (-55°C+125°C); Gamme: X7R; Package: 402; Part Number: 0-00-300071; Temp: (-55°C+125°C); Tension: 16V; Tol: 10%
C24 = CAPA: Alt_Symbols: 0402C; Designation: Capacitor 0402 2.2uF 20% 10V X5R (-55°C+85°C); Gamme: X5R; Package: 402; Part Number: 0-00-300104; Temp: (-55°C+85°C); Tension: 10V; Tol: 20%
C15 C17 C39 C45 = CAPA: Alt_Symbols: 0402C; Designation: Capacitor 0402 4.7uF 10% 10V X5R (-55°C+85°C); Gamme: X5R; Package: 402; Part Number: 0-00-300143; Tension: 10V; Tol: 10%
C3-C5 C9 C12 C14 C19 C21 C25 C26 C37 C42 C43 C46 C47 = CAPA: Alt_Symbols: 0402C; Designation: Capacitor 0402 100nF 10% 10V X5R (-55°C+85°C); Gamme: X5R; Package: 402; Part Number: 0-00-300052; Temp: (-55°C+85°C); Tension: 10V; Tol: 10%
D2 = PRTR5V0U2AX: Designation: Diode PRTR5V0U2AX (SOT-143B) - PRTR5V0U2AX  (-40°C to 85°C); Part Number: 0-00-402852; Part Type: DIODE; Temp: (-40°C to 85°C)
D4 = DIODE_SCHOTTKY: Designation: Diode Schoktty PMEG3020CEP (SOD-128); Manufacturer_reference: NXP (PMEG3020CEP,115); Package: SOD-128; Part Number: 0-00-401760; Part Type: DIODE
D13 D14 = DIODE2A1K_SCHOT: Designation: Diode Schoktty BAT754C (SOT23) - BAT754C; Part Number: 0-00-402573; Part Type: DIODE
D1 DS1-DS6 DS8 = LED: Designation: LED 0603 RED LS-Q976 (-30°C to 85°C); Manufacturer_reference: OSRAM (LS Q976); Package: 0603; Part Number: 0-00-001292; Supplier: RADIOSPARES; Temp: (-30°C to 85°C)
FE1 = FERRITE_2: Designation: Ferrite Bead (220R - 100MHz); Manufacturer_reference: MURATA (BLM18PG221SN1D); Package: BLM18; Part Number: 0-00-002187; Part Type: FERRITE
IC1 = TLV702_SOT: Designation: 2.5V Regulator TLV70225DBVR (SOT-23(5)) - (-40°C to +125°C); Manufacturer_reference: TEXAS INSTRUMENTS (TLV70225DBVR); Package: SOT-23; Part Number: 0-00-403918; Part Type: REGULATOR; Temp: (-40°C to +125°C)
IC5 = LP2992: Designation: 3.3V Regulator LP2992AIM5-3.3/NOPB (SOT-23(5)); Manufacturer_reference: TEXAS INSTRUMENTS (LP2992AIM5-3.3/NOPB); Package: SOT-23; Part Number: 0-00-401103; Part Type: REGULATOR
J4 = JACK2.1_H_NC4: Designation: Connector DC Power 2.1mm Socket SMT; Manufacturer_reference: LUMBERG (1613 14); Package: JACK; Part Number: 0-00-202647; Part Type: CONNECTOR
J5 J14 JP2 JP3 JP5 JP6 = bar_1x3_MD_CAV_1-2: Designation: Header Single Row 3Pts Straight 2mm00 + BUBBLE-8I; Manufacturer_reference: HARWIN (M22-2510305); Package: 2MM; Part Number: 0-00-200117_CAV_BLACK; Part Type: CON_2MM
J7 J11-J13 = BATCON: Designation: Connector - SMT Battery Clip AAA (x2); Manufacturer: Keystone; Package: CLIP_AAA; Part Type: CONNECTOR; Part number: 0-00-100190_x2; REF.Manufacturer: 55; manufacturer_reference: KEYSTONE (55), RAMSES S.A.S (55)
J2 J15 = USB_MINI-B: Designation: Mini-B USB connector (SMD); Manufacturer_reference: MOLEX (0675031020); Part Number: 0-00-202936; Part Type: USB
CH4 JS1-JS3 JS5-JS11 = Chevron_0603_f_cop: Designation: !!! Not Connected !!! (Copper Close By Default); PACKAGE: 603; Part Number: 0-00-3CHEVRON-F-COPPER; Part Type: CHEVRON
R51 = RES: Alt_Symbols: 0402R; Designation: Resistor 0402 3R30 1% 100ppm -; PACKAGE: 402; PPM: 100ppm; Part Number: 0-00-304913; TOL: 1%; Type: CMS
R7 R8 R41 R44 R45 R49 R50 R52-R54 R59 R78 R80 = RES: Designation: !!! NOT CONNECTED !!!; PACKAGE: 402; Part Number: 0-00-3NC_R0402
R61 = RES: Alt_Symbols: 0402R; Designation: Resistor 0402 270R 1% 100ppm -; PACKAGE: 402; PPM: 100ppm; Part Number: 0-00-302048; TOL: 1%; Type: CMS
R67 R81-R83 = RES: Designation: Resistor 0402 680R 1% 100ppm -; MANUFACTURER_REFERENCE: YAGEO (PHYCOMP) (RC0402FR-07680RL); PACKAGE: 402; PPM: 100ppm; Part Number: 0-00-302143A; TOL: 1%; Type: CMS
RG1 = LM1117: Designation: Integrated Circuit LM1117DT-5.0/NOPB (TO-252); Manufacturer_reference: TEXAS INSTRUMENTS (LM1117DT-5.0/NOPB); Package: TO-252; Part Number: 0-00-400956; Part Type: IC
C13 C20 C27 C28 C44 = CAPA: Alt_Symbols: 0402C; Designation: Capacitor 0402 10uF 20% 6V3 X5R (-55°C+85°C); Gamme: X5R; Package: 402; Part Number: 0-00-300050; Temp: (-55°C+85°C); Tension: 6V3; Tol: 20%
C40 C41 = CAPA: Alt_Symbols: 0402C; Designation: Capacitor 0402 27pF +/-0.25pf 50V; Package: 402; Part Number: 0-00-305173; Tension: 50V; Tol: 5%
FE2 FE3 = FERRITE_2: Designation: Ferrite Bead (470R - 100MHz); Manufacturer_reference: MURATA (BLM18PG471SN1D); Package: BLM18; Part Number: 0-00-000446A; Part Type: FERRITE
IC2 = LPC4322_TFBGA100: Designation: Integrated Circuit Debug Probe MCU LPC4322JET100 (TFBGA100); Manufacturer_reference: NXP (LPC4322JET100); Package: TFBGA100; Part Number: 0-00-4LPC4322JET100; Part Type: IC; Temp: (-40°C to +125°C); Color: Default; Location X-Coordinate: 0; Location Y-Coordinate: 0; Power Pins Visible: False; Primitive: DEFAULT; SPLIT_INST: TRUE; SWAP_INFO: (S1+S2+S3+S4+S5)
R27 R30 R33 R66 = RES: Alt_Symbols: 0402R; Designation: Resistor 0402 12K0 1% 100ppm -; MANUFACTURER_REFERENCE: VISHAY (CRCW040212K0FKED); PACKAGE: 402; PPM: 100ppm; Part Number: 0-00-301977A; SUPPLIER: RADIOSPARES; TOL: 1%; Type: CMS
R1-R3 R5 R14 R25 R28 R31 R32 R35 R36 R55 R56 R58 R71 R73 R75 R77 R85-R98 RX1-RX12 = RES: Alt_Symbols: 0402R; Designation: Resistor 0402 0R - - -; PACKAGE: 402; Part Number: 0-00-301956; Type: CMS
R4 R12 R13 R17 R26 R29 R63 R65 = RES: Alt_Symbols: 0402R; Designation: Resistor 0402 100K 1% 100ppm -; PACKAGE: 402; PPM: 100ppm; Part Number: 0-00-301958; TOL: 1%; Type: CMS
R9 R15 R16 R20-R24 R34 R37-R40 R46 R47 R57 R64 R69 R84 = RES: Alt_Symbols: 0402R; Designation: Resistor 0402 2K20 1% 100ppm -; PACKAGE: 402; PPM: 100ppm; Part Number: 0-00-302056; TOL: 1%; Type: CMS
Y1 = XTAL: Designation: ABLS2-12.000MHz-D4Y-T (0°C to 70°C); Manufacturer_reference: ABRACON (ABLS2-12.000MHz-D4Y-T); Package: HC/49US; Part Number: 0-00-403914; Part Type: CLOCK; Temp: (0°C to 70°C)
Z1-Z8 = PLOT: Designation: !!! Not Connected !!!; Part Number: 0-00-2PLOT090_NC
ANT2 = Antenna: Designation: !!! COPPER PRINTED BOARD !!!; Package: ANTENNA; Part Type: MISC; Part number: 0-00-0ANT_COP_NC
BP1 SW2 SW4 = BP_EVQQ2: Designation: Switch tactile SPST - EVQ-Q2P03W (EVQQ2); Manufacturer_reference: PANASONIC (EVQ-Q2P03W); Package: EVQQ2; Part Number: 0-00-001838; Part Type: COMMUTATOR
C16 C18 = CAPA: Alt_Symbols: 0402C; Designation: Capacitor 0402 15pF 1% 200V COG/NPO (-55°C+125°C); Gamme: COG/NPO; MANUFACTURER_REFERENCE: American Technical Cerami (600L150FT200T); Package: 402; Part Number: 0-00-300089A; Supplier: MOUSER ELECTRONICS; Temp: (-55°C+125°C); Tension: 200V; Tol: 1%
D7 = LED: Designation: LED 0603 RED/ORANGE ASMT-RH45-AQ502; Manufacturer_reference: AVAGO TECHNOLOGIES (ASMT-RH45-AQ502); Package: 0603; Part Number: 0-00-001361; Supplier: FARNELL
IC3 = MX25R8035F_RST: Designation: Integrated Circuit QSPI Flash 8Mbit MX25R8035FM2IL0 (8-SOP); Manufacturer_reference: MACRONIX (MX25R8035FM2IL0); Package: 8-SOP; Part Number: 0-00-403917; Part Type: IC; Temp: (-40°C to +85°C)
IC4 = NT3H1101: Designation: Integrated Circuit NT3H2111W0FHK (8-XQFN); Manufacturer_reference: NXP (NT3H2111W0FHK); Package: 8-XQFN; Part Number: 0-00-404573; Part Type: IC
R42 R43 R48 R62 = RES: Alt_Symbols: 0402R; Designation: Resistor 0402 4K7 1% 100ppm -; MANUFACTURER_REFERENCE: PANASONIC (ERJ-2RKF4701X); PACKAGE: 402; PPM: 100ppm; Part Number: 0-00-302116A; SUPPLIER: DIGIKEY CORPORATION; TOL: 1%; Type: CMS
R60 = RES: Alt_Symbols: 0402R; Designation: Resistor 0402 10K0 1% 100ppm -; PACKAGE: 402; PPM: 100ppm; Part Number: 0-00-301963; TOL: 1%; Type: CMS
TP1 TP3 TP5 TP6 = PLOT: Designation: !!! Not Connected !!!; Part Number: 0-00-2PLOT050_NC
CH5 CH6 = CHEVRON_0603_F_RESI: Designation: Resistor 0603 0R 1% 100ppm -; Manufacturer_reference: VISHAY (CRCW06030000Z0EA); Package: 603; Part Number: 0-00-302172C; Part Type: CHEVRON; Supplier: FARNELL
CN1 CN3 = HEADER_8P: Designation: SOCKET, 1ROW, 8WAY Vertical; Manufacturer_reference: SAMTEC (BCS-108-L-S-TE); Package: 2MM54; Part Number: 0-00-200781A; Part Type: CON_2MM54
CN2 = HEADER_10P: Designation: SOCKET, 1ROW, 10WAY Vertical; Manufacturer_reference: SAMTEC (BCS-110-L-S-TE); Package: 2MM54; Part Number: 0-00-203983; Part Type: CON_2MM54
CN4 = HEADER_6P: Designation: SOCKET, 1ROW, 6WAY Vertical; Manufacturer_reference: SAMTEC (BCS-106-L-S-TE); Package: 2MM54; Part Number: 0-00-200779; Part Type: CON_2MM54
J3 = HEADER_2X17: Designation: Header Double Row 34Pts Straight 2mm54 (2x17) (ATTENTION : 2x40Pts); Manufacturer_reference: E-TEC (SL2-080-S125/01-55); Package: 2MM54; Part Number: 0-00-200101A; Part Type: CON_2MM54
JM1 JM2 = CON2X10_HE10_AMPMODU: Designation: Header SMT 2 X 10 Way; Manufacturer: HARWIN; Package: 1MM27; Part Type: CON_1MM27; Part number: 0-00-202720; REF.Manufacturer: M50-3601042; Supplier: RADIOSPARE; manufacturer_reference: HARWIN (M50-3601042)
1 = BUBBLE: Designation: Printed Circuit Board : OM15076-3 (NXP : Carrier board JN5189); Manufacturer_reference: PCB2455-3; Part Number: 0-CI-001583; Part Type: BUBBLE-001_CI; Supplier: ASCO
8D_X9 = BUBBLE: Designation: (Cavalier)SULLINS Jumper, 2mm; Manufacturer_reference: SULLINS (NPN02SXLN-RC); Part Number: PN-NPN02SXLN-RC; Part Type: BUBBLE-08_JUMPER_CAV
M6 = MNT_HOLE: Alt_Symbols: tp2-ha_apps; Designation: !!! Not Connected !!! (ANTENNA HOLE); Package: ANTENNA; Part Number: 0-00-0ANT_HOLE_NC; Part Type: MISC
CH1-CH3 = Chevron_0603_open: Designation: !!! Not Connected !!! (Open By Default); Package: 603; Part Number: 0-00-3CHEVRON-NC; Part Type: CHEVRON
IC6 = SN74AV2CT45DCTR: Designation: Integrated Circuit Level shifter SN74AVC2T45DCTR (SM8); Manufacturer_reference: TEXAS INSTRUMENTS (SN74AVC2T45DCTR); Package: SM8; Part Number: 0-00-403923; Part Type: IC; Temp: (-40°C to +85°C)
IC7-IC9 IC13 = SN74AVC1T45: Designation: Integrated Circuit Level shifter 74LVC1T45GW (SOT363); Manufacturer_reference: NXP (74LVC1T45GW); Package: SOT363; Part Number: 0-00-403919; Part Type: IC; Temp: (-40°C to +125°C)
IC10 = 74LVC1G07: Designation: Integrated Circuit Buffer 74LVC1G07GW (TSSOP5) (SOT353-1); Manufacturer_reference: NXP (74LVC1G07GW,125); Package: SOT353-1; Part Number: 0-00-400213; Part Type: IC; Temp: (-40°C to +125°C)
IC11 = NX3DV2567: Color: Default; Designation: Integrated Circuit 4 pole double throw analog switch NX3DV2567GU (SOT1161-1); Location X-Coordinate: 0; Location Y-Coordinate: 0; Manufacturer_reference: NXP (NX3DV2567GU); NC: 10; Package: SOT1161-1; Part Number: 0-00-403913; Part Type: IC; Power Pins Visible: False; Primitive: DEFAULT; Temp: (-40°C to +125°C)
IC12 = 74LVC1G3157: Designation: Integrated Circuit 2 channel analog Multi/Demultiplexer 74LVC1G3157GW 5SOT363); Manufacturer_reference: NXP (74LVC1G3157GW); Package: SOT363; Part Number: 0-00-403922; Part Type: IC; Temp: (-40°C to +125°C)
IC14 = PESD3V3L5UK: Color: Default; Designation: ESD protection diode arrays PESD3V3L5UK (SOT891) - (-55°C to +150°C); Location X-Coordinate: 0; Location Y-Coordinate: 0; Manufacturer_reference: NXP (PESD3V3L5UK); Package: SOT891; Part Number: 0-00-403916; Part Type: ESD; Power Pins Visible: False; Primitive: DEFAULT; Temp: (-55°C to +150°C)
JP1 = BAR_1X3_MD_CAV_2-3: Designation: Header Single Row 3Pts Straight 2mm00 + BUBBLE-8I; Manufacturer_reference: HARWIN (M22-2510305); Package: 2MM; Part Number: 0-00-200117_CAV23_BLACK; Part Type: CON_2MM
P1 = HEADER_2X5: Designation: Header SMD 2 X 5 Way FTSH-105-01-L-DV-K-P-TR (FSTH) - (-55°C to +125°C); Manufacturer_reference: SAMTEC (FTSH-105-01-L-DV-K-P-TR); Package: 1MM27; Part Number: 0-00-201448; Part Type: CON_1MM27; Temp: (-55°C to +125°C)
R10 R11 R18 R19 R68 R70 = RES: Alt_Symbols: 0402R; Designation: Resistor 0402 100R 1% 100ppm -; PACKAGE: 402; PPM: 100ppm; Part Number: 0-00-301960; TOL: 1%; Type: CMS
R76 = RES: Alt_Symbols: 0402R; Designation: Resistor 0402 1K50 1% 100ppm -; MANUFACTURER_REFERENCE: VISHAY (CRCW04021K50FKEAHP); PACKAGE: 402; PPM: 100ppm; Part Number: 0-00-302012B; SUPPLIER: FARNELL; TOL: 1%; Type: CMS
C29 C30 = CAPA: Alt_Symbols: 0402C; Designation: Capacitor 0402 47pF 1% 50V COG/NPO (-55°C+125°C); Gamme: COG/NPO; MANUFACTURER_REFERENCE: AVX (04025A470FAT2A); Package: 402; Part Number: 0-00-300163B; Supplier: FARNELL; Temp: (-55°C+125°C); Tension: 50V; Tol: 1%
C33 = CAPA: Alt_Symbols: 0402C; Designation: Capacitor 0402 470pF 5% 50V COG/NPO (-55°C+125°C); Gamme: COG/NPO; Package: 402; Part Number: 0-00-300159; Temp: (-55°C+125°C); Tension: 50V; Tol: 5%
C34 = CAPA: Alt_Symbols: 0402C; Designation: Capacitor 0402 10nF 5% 16V X7R (-55°C+125°C); Gamme: X7R; Package: 402; Part Number: 0-00-300077; Temp: (-55°C+125°C); Tension: 16V; Tol: 5%
C35 C36 = CAPA: Alt_Symbols: 0402C; Designation: Capacitor 0402 47pF 1% 50V COG/NPO (-55°C+125°C); Gamme: COG/NPO; Package: 402; Part Number: 0-00-300163; Temp: (-55°C+125°C); Tension: 50V; Tol: 1%
C48 = CAPA: Alt_Symbols: 0402C; Designation: !!! NOT CONNECTED !!!; Package: 402; Part Number: 0-00-3NC_C0402
C49 = CAPA: Alt_Symbols: 0402C; Designation: Capacitor 0402 100nF 5% 10V X7R (-55°C+125°C); Gamme: X7R; Package: 402; Part Number: 0-00-305250; Temp: (-55°C+125°C); Tension: 10V; Tol: 5%
D3 D5 = BAT754: Designation: Diode Schoktty BAT754 (SOT23); Part Number: 0-00-403888; Part Type: DIODE
IC18 IC24 = 74AVC4TD245: Designation: Integrated Circuit 4 bit level shifter 74AVC4TD245BQ (SOT763-1); Manufacturer_reference: NXP (74AVC4TD245BQ); Package: SOT763-1; Part Number: 0-00-403912; Part Type: IC; Temp: (-40°C to +125°C)
IC19 = ADC122S021: Designation: Integrated Circuit 2 channel 200ksps 12bit ADC122S021 (VSSOP8); Manufacturer_reference: TEXAS INSTRUMENTS (ADC122S021CIMM/NOPB); Package: VSSOP8; Part Number: 0-00-403915; Part Type: IC; Temp: (-40°C to +85°C)
IC20 = 74LVC1G53: Designation: Integrated Circuit 2 channel analog Multi/Demultiplexer 74LVC1G53DC (SOT765-1); Manufacturer_reference: NXP (74LVC1G53DC); Package: SOT765-1; Part Number: 0-00-403924; Part Type: IC; Temp: (-40°C to +125°C)
IC21 = MAX9634_SOT: Designation: Integrated Circuit current sense amplifier MAX9634TEUK+T (SOT-23(5)); Manufacturer_reference: MAXIM (MAX9634TEUK+T); Package: SOT-23; Part Number: 0-00-403920; Part Type: IC; Temp: (-40°C to +85°C)
IC22 = FT230XS: Designation: Integrated Circuit FT230XS (SSOP-16); Manufacturer_reference: FTDI Chip (FT230XS), FTDI Chip (FT230XS-R), FTDI Chip (FT230XS-U); Package: SSOP-16; Part Number: 0-00-400790; Part Type: IC
JP4 JP7 = bar_1x4_MD_CAV_2-3: Designation: Header Single Row 4Pts Straight 2mm00 + BUBBLE-8I; Manufacturer_reference: HARWIN (M22-2510405); Package: 2MM; Part Number: 0-00-204744_CAV23_BLACK; Part Type: CON_2MM
TP2 = PLOT: Designation: !!! Not Connected !!!; Part Number: 0-00-2PLOT10_NC

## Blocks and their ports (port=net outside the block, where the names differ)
USER INTERFACES MEMORY = schematic FONCTION, on sheet PAGE1: LA, LB, PIO_3/SPI1_SSELN0=PIO_3, PIO_0/SPI1_SCK=PIO_0, PIO_11/I2C0_SDA=PIO_11, PIO_10/I2C0_SCL=PIO_10, GND, VDD_TRGT, FD, PIO_1/SPI1_MISO=PIO_1, PIO_18/SPIFI_CLK_QSPI=PIO_18, PIO_19/SPIFI_IO0_QSPI=PIO_19, PIO_17/SPIFI_IO3_QSPI=PIO_17, PIO_21_SPIFI_IO1_QSPI=PIO_21, PIO_20/SPIFI_IO2_QSPI=PIO_20, PIO_16/SPIFI_CSN_QSPI=PIO_16
CONNECTORS = schematic CONNECTORS, on sheet PAGE1: PIO_0/SPI1_SCK=PIO_0, PIO_2/SPI1_MOSI=PIO_2, PIO_3/SPI1_SSELN0=PIO_3, LB, LA, PIO_7/PWM7-PD=PIO_7, PIO_10/I2C0_SCL=PIO_10, RSTN, PIO_11/I2C0_SDA=PIO_11, PIO_5/ISP_ENTRY=PIO_5, PIO_13/SWDIO=PIO_13, PIO_4/PWM4-PU=PIO_4, PIO_6/PWM6-PD=PIO_6, PIO_12/SWCLK=PIO_12, FD, VIN, VDD_TRGT, VBAT, VCC3.3V, GND, VCC5V, PIO_14/ADC0=PIO_14, PIO_15/ADC1=PIO_15, PIO_1/SPI1_MISO=PIO_1, PIO_8/USART0_TXD=PIO_8, PIO_9/USART0_RXD=PIO_9, PIO_18/SPIFI_CLK_QSPI=PIO_18, PIO_19/SPIFI_IO0_QSPI=PIO_19, PIO_17/SPIFI_IO3_QSPI=PIO_17, PIO_21_SPIFI_IO1_QSPI=PIO_21, PIO_20/SPIFI_IO2_QSPI=PIO_20, PIO_16/SPIFI_CSN_QSPI=PIO_16
POWER-SUPPLY = schematic ALIM, on sheet PAGE1: USB_DP, USB_DM, GND, USB_ID, VCC3.3V, VIN, VDD_SENSE, VDD_TRGT, VBAT, USB_VBUS_LINK, +2.5V_LINK, VCC5V, VCC_USB_FTDI
LPC-LINK2-DEBUG-PROBE = schematic SONDE, on sheet PAGE1: BRIDGE_T_MOSI=PIO_2, BRIDGE_SCL=PIO_10, USB_DP, USB_DM, USB_VBUS_LINK, USB_ID, +2.5V_LINK, VDD_TRGT, GND, nRESET_TRGT=RSTN, VDD_SENSE, BRIDGE_T_SSEL=PIO_3, ISP_EN_TRGT=PIO_5, ISP_TX_TRGT=PIO_8, ISP_RX_TRGT=PIO_9, SWDIO_TRGT=PIO_13, SWDCLK_TRGT=PIO_12, SWO_TRGT=PIO_14, BRIDGE_SDA=PIO_11, BRIDGE_T_INTR=PIO_7, PIO_6, USART1_TX/BRIDGE_T_SCK=PIO_0, USART1_RX/BRIDGE_T_MISO=PIO_1, VCC_USB_FTDI

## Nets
+2.5V_LINK: C9.1 C10.1 C12.1 C13.1 C14.1 C17.1 C20.1 C21.1 C22.1 C45.1 C46.2 FE2.1 IC2.B2(VDDA) IC2.C5(VBAT) IC2.D1(USB0_VDDA3V3_DRVR) IC2.D2(USB0_VDDA3V3) IC2.F10(VDDIO_1) IC2.K5(VDDIO_2) IC6.1(VCCA) IC7.1(VCCA) IC8.1(VCCA) IC9.1(VCCA) IC10.5(VCC) IC13.1(VCCA) IC18.1(VCCA) IC24.1(VCCA) JP6.1 JS3.2 R4.2 R21.2 R22.2 R29.2 R30.1 R33.1 R53.1 R65.1 R66.1 R81.1 R82.1 Z4.1
GND: BP1.A BP1.AP C1.2(M) C2.2(M) C3.2 C4.2 C5.2 C6.2(M) C7.2(M) C8.1 C9.2 C10.2 C11.2 C12.2 C13.2 C14.2 C15.2 C17.2 C19.2 C20.2 C21.2 C22.2 C23.2 C24.2 C25.2 C26.2 C27.2 C28.2 C29.2 C30.2 C31.2 C32.2 C33.2 C34.2 C35.2 C36.2 C37.2 C38.2 C39.2 C40.1 C41.2 C42.2 C43.2 C44.1 C45.2 C46.1 C47.2 C48.2 C49.1 CN2.7 CN3.6 CN3.7 D1.K D2.1 D7.K IC1.2(GND) IC2.C2(VSSA) IC2.C8(VSSIO_1) IC2.D3(USB0_VSSA_TERM) IC2.D4(VSSIO_2) IC2.D5(VSSIO_3) IC2.F2(USB0_VSSA_REF) IC2.G8(VSSIO_4) IC2.J3(VSSIO_5) IC2.J6(VSSIO_6) IC3.4(GND) IC4.2(GND) IC5.2(GND) IC6.4(GND) IC7.2(GND) IC7.5(DIR) IC8.2(GND) IC9.2(GND) IC10.3(GND) IC11.1(Y0) IC11.5(Y0) IC11.6(GND) IC11.9(Y0) IC11.15(Y1) IC12.2(GND) IC13.2(GND) IC13.5(DIR) IC14.2(GND) IC18.8(GND) IC18.17(DIE_PAD) IC19.3(GND) IC20.2(~{E}) IC20.3(GND1) IC20.4(GND2) IC21.1(GND) IC21.2(GND) IC22.5(GND1) IC22.13(GND2) IC24.8(GND) IC24.17(DIE_PAD) J2.5(GND) J2.A(SHIELD) J2.B(SHIELD) J2.C(SHIELD) J2.D(SHIELD) J3.1 J3.2 J3.4 J3.32 J3.33 J3.34 J4.2 J4.3 J7.3 J7.4 J15.5(GND) J15.A(SHIELD) J15.B(SHIELD) J15.C(SHIELD) J15.D(SHIELD) JM1.19 JP1.2 JP5.2 P1.3 P1.5 R1.1 R7.2 R9.2 R15.1 R16.1 R23.1 R24.1 R27.1 R34.1 R39.2 R40.1 R54.2 R69.2 R78.2 R80.2 R83.2 RG1.1(GND) SW2.B SW2.BP SW4.B SW4.BP TP2.1 Z1.1
VBAT: J3.31 JM1.17 JS1.2
VBAT3V: J5.3 J12.3 J12.4 J13.1 J13.2
VBAT4V5: D14.1(A1) J11.3 J11.4 J12.1 J12.2
VBAT6V: J11.1 J11.2 JP3.3
VCC3.3V: C7.1(P) C27.1 C28.1 C31.1 CN3.4 IC5.5(VOUT) IC19.2(VA) IC20.8(VCC) J5.1
VCC5V: CN3.5 D13.3(C) D14.3(C) JP3.1
VCC5V_USB: C39.1 C42.1 D13.1(A1) FE1.1 IC1.1(VIN) IC1.3(EN) R61.2
VCC_USB_FTDI: D13.2(A2) FE3.2 IC22.11(~{RST}) IC22.12(VCC)
VDD_SENSE: J14.2 JS1.1 JS6.1 R51.2
VDD_TRGT: C3.1 C8.2 C32.1 C37.1 C47.1 C49.2 CN3.2 DS1.A IC3.8(VCC) IC4.6(VCC) IC11.14(VCC) IC12.5(VCC) IC13.6(VCCB) IC18.16(VCCB) IC22.3(VCCIO) IC22.10(3V3OUT) IC24.16(VCCB) J5.2 J14.1 JP2.1 JS5.1 JS7.1 JS8.1 JS10.1 R26.2 R41.2 R42.2 R43.2 R46.1 R47.1 R51.1 R57.1 R60.1 R63.1 R64.1 R84.1
VDD_TRGT_SWD: C4.1 C5.1 C25.1 C26.1 C44.2 IC6.8(VCCB) IC7.6(VCCB) IC8.6(VCCB) IC9.6(VCCB) JP2.2 P1.1 R12.2 R13.2 R17.2
VIN: C2.1(P) CN3.8 D4.2(CATHODE) J3.29 R52.1 RG1.3(IN)
CONNECTORS/ANT_SEL: J3.3 JM2.18
CONNECTORS/CN1_0: CN1.1 R71.2
CONNECTORS/CN1_1: CN1.2 R14.2
CONNECTORS/CN1_2: CN1.3 R94.2
CONNECTORS/CN1_3: CN1.4 R95.2
CONNECTORS/CN1_4: CN1.5 R96.2
CONNECTORS/CN1_5: CN1.6 R97.2
CONNECTORS/CN1_6: CN1.7 R36.2
CONNECTORS/CN1_7: CN1.8 R35.2
CONNECTORS/CN2_1: CN2.1 R85.2
CONNECTORS/CN2_2: CN2.2 R86.2
CONNECTORS/CN2_3: CN2.3 R87.2
CONNECTORS/CN2_4: CN2.4 R88.2
CONNECTORS/CN2_5: CN2.5 R89.2
CONNECTORS/CN2_6: CN2.6 R90.2
CONNECTORS/CN2_8: CN2.8 R91.2
CONNECTORS/CN2_9: CN2.9 R92.2
CONNECTORS/CN2_10: CN2.10 R93.2
CONNECTORS/CN4_1: CN4.1 R55.2
CONNECTORS/CN4_2: CN4.2 R3.2
CONNECTORS/CN4_3: CN4.3 R73.2
CONNECTORS/CN4_4: CN4.4 R5.2
CONNECTORS/CN4_5: CN4.5 R77.2
CONNECTORS/CN4_6: CN4.6 R75.2
CONNECTORS/LNA_BYPASS: J3.5 JM2.20
CONNECTORS/PIO_8: CH5.2 J3.15 JM1.5
CONNECTORS/PIO_9: CH6.2 J3.16 JM1.7
CONNECTORS/PIO_16: J3.23 R73.1 RX5.1
CONNECTORS/PIO_16/SPIFI_CSN: JM2.11 R36.1 RX3.1 RX5.2
CONNECTORS/PIO_17: J3.24 R5.1 RX12.2
CONNECTORS/PIO_17/SPIFI_IO3: JM1.12 RX11.2 RX12.1
CONNECTORS/PIO_18: J3.25 R85.1 RX6.1
CONNECTORS/PIO_18/SPIFI_CLK: JM1.10 RX4.1 RX6.2
CONNECTORS/PIO_19: J3.26 R91.1 RX2.1
CONNECTORS/PIO_19/SPIFI_IO0: JM1.8 RX1.1 RX2.2
CONNECTORS/PIO_20: J3.27 R77.1 RX10.2
CONNECTORS/PIO_20/SPIFI_IO2: JM1.6 RX9.2 RX10.1
CONNECTORS/PIO_21: J3.28 R75.1 RX8.2
CONNECTORS/PIO_21_SPIFI_IO1: JM1.2 RX7.2 RX8.1
FD: IC4.4(FD) J3.6 R60.2
LA: C18.1 JM2.4 R32.2
LB: C18.2 JM2.2 R58.1
LPC-LINK2-DEBUG-PROBE/BOOT0_LED: IC2.K2(P1[1]_/GPIO0[8]/CTOUT_7/EXTBUS_A6/SGPIO8) R20.2 R21.1
LPC-LINK2-DEBUG-PROBE/BOOT1: IC2.K1(P1[2]_/GPIO0[9]/CTOUT_6/EXTBUS_A7/SGPIO9) R23.2
LPC-LINK2-DEBUG-PROBE/BOOT2: IC2.C6(P2[8]_/SGPIO15/CTOUT_0/U3_DIR/EXTBUS_A8/GPIO5[7]) R22.1
LPC-LINK2-DEBUG-PROBE/BOOT3: IC2.B10(P2[9]_/GPIO1[10]/CTOUT_3/U3_BAUD3/EXTBUS_A0) R24.2
LPC-LINK2-DEBUG-PROBE/BOOT_FLASH: IC2.C10(P2[7]_/GPIO0[7]/CTOUT_1/U3_UCLK/EXTBUS_A9) JP5.1
LPC-LINK2-DEBUG-PROBE/BRIDGE_INTR_DIR: IC2.J7(P1[11]_/GPIO1[4]/U1_CTS/CTOUT_15/EXTBUS_D4) IC18.10(DIR) R39.1 R53.2
LPC-LINK2-DEBUG-PROBE/BRIDGE_L_INTR: IC2.J5(P1[9]_/GPIO1[2]/U1_RTS/CTOUT_11/EXTBUS_D2) R38.1
LPC-LINK2-DEBUG-PROBE/BRIDGE_L_MISO: IC2.J1(P1[3]_/GPIO0[10]/CTOUT_8/SGPIO10/EXTBUS_OE) IC24.3(A)
LPC-LINK2-DEBUG-PROBE/BRIDGE_L_MOSI: IC2.J2(P1[4]_/GPIO0[11]/CTOUT_9/SGPIO11/EXTBUS_BLS0) IC18.6(A)
LPC-LINK2-DEBUG-PROBE/BRIDGE_L_SCK: IC2.K9(P1[19]_/ENET_TX_REF_CLK/SSP1_SCK/CLKOUT/I2S1_RX_SCK) IC18.4(A)
LPC-LINK2-DEBUG-PROBE/BRIDGE_L_SSEL: IC2.K10(P1[20]_/GPIO0[15]/SSP1_SSEL/NC/ENET_TXD1) IC18.3(A)
LPC-LINK2-DEBUG-PROBE/CUR_MEAS_SEL: IC2.H1(P1[0]_/GPIO0[4]/CTIN_3/EXTBUS_A5) IC20.5(S)
LPC-LINK2-DEBUG-PROBE/FTDI_RX: JP4.2 R2.1
LPC-LINK2-DEBUG-PROBE/FTDI_TX: JP7.2 R98.1
LPC-LINK2-DEBUG-PROBE/IF_DETECT: P1.9 R1.2 R76.1
LPC-LINK2-DEBUG-PROBE/IF_ISPEN: C48.1 D5.1(ANODE) DS8.K P1.7 R19.2 R25.1 R31.2
LPC-LINK2-DEBUG-PROBE/IF_JTAG_TDI: IC14.1(A1) P1.8 R11.2
LPC-LINK2-DEBUG-PROBE/IF_RST: CH2.1 IC11.7(Y1) IC14.3(A1) P1.10 R18.2
LPC-LINK2-DEBUG-PROBE/IF_TCK_SWCLK: CH1.1 IC11.3(Y1) IC14.6(A1) P1.4 R10.2
LPC-LINK2-DEBUG-PROBE/IF_TDO_SWO: CH3.1 IC7.4(B) IC11.11(Y1) IC14.4(A1) P1.6 R12.1
LPC-LINK2-DEBUG-PROBE/IF_TMS_SWDIO: CH4.1 IC14.5(A1) P1.2 R70.2
LPC-LINK2-DEBUG-PROBE/ISP_CTRL: IC2.A9(P2[11]_/GPIO1[11]/CTOUT_5/U2_RXD/EXTBUS_A2) IC10.2(A)
LPC-LINK2-DEBUG-PROBE/JTAG_RESET: IC2.D10(P2[5]_/SGPIO14/CTIN_2/USB1_VBUS/ADCTRIG1) IC9.3(A)
LPC-LINK2-DEBUG-PROBE/JTAG_RESET_TXEN: IC2.G9(P2[6]_/SGPIO7/U0_DIR/EXTBUS_A10/USB0_IND0) IC9.5(DIR) R16.2
LPC-LINK2-DEBUG-PROBE/JTAG_TDI: IC2.J10(P1[18]_/GPIO0[13]/U2_DIR/NC/ENET_TXD0) IC6.3(A2)
LPC-LINK2-DEBUG-PROBE/LPC_RX_BUF: IC12.4(Z) JP4.4
LPC-LINK2-DEBUG-PROBE/LPC_TX_BUF: IC13.4(B) JP7.4
LPC-LINK2-DEBUG-PROBE/nTRST_LINK2: IC2.B4(nTRST) R30.2 Z3.1
LPC-LINK2-DEBUG-PROBE/SSP0_MISO_LINK: IC2.C7(P3[6]_/GPIO0[6]/SPI_MISO/SSP0_SSEL/SPIFI_MISO) IC19.7(DOUT)
LPC-LINK2-DEBUG-PROBE/SSP0_MOSI_LINK: IC2.D7(P3[7]_//SPI_MOSI/SSP0_MISO/SPIFI_MOSI) IC19.6(DIN)
LPC-LINK2-DEBUG-PROBE/SSP0_SCK_LINK: IC2.A7(P3[3]_//SPI_SCK/SSP0_SCK/SPIFI_SCK) IC19.8(SCLK)
LPC-LINK2-DEBUG-PROBE/SSP0_SSEL_LINK: IC2.E7(P3[8]_//SPI_SSEL/SSP0_MOSI/SPIFI_CS) IC19.1(~{CS})
LPC-LINK2-DEBUG-PROBE/SWDCLK_LINK2: IC2.H2(TCK/SWDCLK) R34.2 Z5.1
LPC-LINK2-DEBUG-PROBE/SWDIO_LINK2: IC2.C4(TMS/SWDIO) Z6.1
LPC-LINK2-DEBUG-PROBE/TARGET_UART_CTRL: IC2.F5(P2[2]_/SGPIO6/U0_UCLK/EXTBUS_A11/USB0_IND1) IC12.6(S) R69.1
LPC-LINK2-DEBUG-PROBE/TARGET_UART_RXD: DS6.K IC2.G10(P2[0]_/SGPIO4/U0_TXD/EXTBUS_A13/USB0_PWR_EN) IC12.1(Y1)
LPC-LINK2-DEBUG-PROBE/TARGET_UART_TXD: IC2.G7(P2[1]_/SGPIO5/U0_RXD/EXTBUS_A12/USB0_PWR_FAULT) R68.1
LPC-LINK2-DEBUG-PROBE/TCK_SWCLK: IC2.H10(P1[17]_/GPIO0[12]/U2_UCLK/NC/ENET_MDIO) IC6.2(A1)
LPC-LINK2-DEBUG-PROBE/TDO_SWO: IC2.J8(P1[14]_/GPIO1[7]/U1_RXD/NC/EXTBUS_D7) IC7.3(A)
LPC-LINK2-DEBUG-PROBE/TMS_SWDIO: IC2.K4(P1[6]_/GPIO1[9]/CTIN_5/NC/EXTBUS_WE) IC8.3(A)
LPC-LINK2-DEBUG-PROBE/TMS_SWDIO_TXEN: IC2.J4(P1[5]_/GPIO1[8]/CTOUT_10/NC/EXTBUS_CS0) IC8.5(DIR) R15.2
PIO_0: DS2.K IC18.13(B) J3.7 JM2.1 JP7.1 R90.1
PIO_1: BP1.B BP1.BP IC24.14(B) J3.8 JM1.18 JP4.1 R47.2 R89.1
PIO_2: IC18.11(B) J3.9 JM2.5 R88.1
PIO_3: DS3.K IC18.14(B) J3.10 JM2.7 R86.1
PIO_4: J3.11 JM1.9 R87.1
PIO_5: J3.12 JM2.3 R25.2
PIO_6: J3.13 JM1.15 R44.1 R95.1
PIO_7: J3.14 JM1.20 R8.1 R35.1 R37.2
PIO_8: CH5.1 JP7.3 R71.1
PIO_9: CH6.1 JP4.3 R14.1
PIO_10: J3.17 JM1.14 JS11.1 R45.2 R48.2 R93.1 R96.1
PIO_11: J3.18 JM2.9 JS2.1 R59.2 R62.2 R92.1 R97.1
PIO_12: CH1.2 IC11.4(Z) J3.19 JM1.1
PIO_13: CH4.2 J3.20 JM1.3
PIO_14: CH3.2 IC11.12(Z) J3.21 JM2.16 R55.1
PIO_15: J3.22 JM2.13 JM2.14 R3.1 R94.1
PIO_16: IC3.1(~{CS}) R63.2 RX3.2
PIO_17: IC3.7(~{RESET}/SIO3) RX11.1
PIO_18: IC3.6(SCLK) RX4.2
PIO_19: IC3.5(SI/SIO0) RX1.2
PIO_20: IC3.3(~{WP}/SIO2) RX9.1
PIO_21: IC3.2(SO/SIO1) RX7.1
PS5V: C1.1(P) D14.2(A2) R52.2 RG1.2(OUT)
RSTN: C33.1 CH2.2 CN3.3 D3.1(ANODE) DS4.K IC11.8(Z) J3.30 JM1.16 R56.2
USB_DM: D2.3 IC2.E2(USB0_DM) J15.2(D-)
USB_DP: D2.2 IC2.E1(USB0_DP) J15.3(D+)
USB_ID: J15.4(OTG_ID) R28.1
USB_VBUS_LINK: IC2.E3(USB0_VBUS) R61.1
LPC-LINK2-DEBUG-PROBE/N46398: IC9.4(B) R17.1 R18.1
LPC-LINK2-DEBUG-PROBE/N46402: IC8.4(B) R13.1 R70.1
LPC-LINK2-DEBUG-PROBE/N46436: IC2.A10(P2[13]_/GPIO1[13]/CTIN_4/NC/EXTBUS_A4) R76.2
LPC-LINK2-DEBUG-PROBE/N46536: IC2.J9(P6[2]_/GPIO3[1]/EXTBUS_CKEOUT1/U0_DIR/I2S0_RX_SDA) R80.1
LPC-LINK2-DEBUG-PROBE/N46544: IC2.F9(P6[5]_/GPIO3[4]/CTOUT_6/U0_RXD/EXTBUS_nRAS) R7.1
LPC-LINK2-DEBUG-PROBE/N46552: IC2.F8(P6[9]_/GPIO3[5]/NC/NC/EXTBUS_nDYCS0) R78.1
LPC-LINK2-DEBUG-PROBE/N46560: IC2.C9(P6[11]_/GPIO3[7]/NC/NC/EXTBUS_CKEOUT0) R9.1
LPC-LINK2-DEBUG-PROBE/N46632: IC6.5(DIR) R4.1
LPC-LINK2-DEBUG-PROBE/N46864: IC6.7(B1) R10.1
LPC-LINK2-DEBUG-PROBE/N46912: IC6.6(B2) R11.1
LPC-LINK2-DEBUG-PROBE/N47280: IC12.3(Y0) TP3.1
LPC-LINK2-DEBUG-PROBE/N48360: IC10.4(Y) R19.1
LPC-LINK2-DEBUG-PROBE/N48368: IC11.2(S) JP1.1 R26.1
LPC-LINK2-DEBUG-PROBE/N50399: C40.2 IC2.C1(XTAL2) Y1.1
LPC-LINK2-DEBUG-PROBE/N50406: C41.1 IC2.B1(XTAL1) Y1.2
LPC-LINK2-DEBUG-PROBE/N50993: IC2.A4(WAKEUP0) R29.1
LPC-LINK2-DEBUG-PROBE/N51038: IC2.A2(ADC0) Z7.1
LPC-LINK2-DEBUG-PROBE/N51356: IC2.A6(DBGEN) R66.2
LPC-LINK2-DEBUG-PROBE/N51365: IC2.B6(nRESET) R33.2
LPC-LINK2-DEBUG-PROBE/N52537: C11.1 C15.1 C19.1 FE2.2 IC2.E4(VDDREG_1) IC2.E5(VDDREG_2) IC2.F4(VDDREG_3)
LPC-LINK2-DEBUG-PROBE/N56295: IC2.D6(I2C0_SCL) JS11.2
LPC-LINK2-DEBUG-PROBE/N56307: IC2.E6(I2C0_SDA) JS2.2
LPC-LINK2-DEBUG-PROBE/N56658: IC2.F3(USB0_RREF) R27.2
LPC-LINK2-DEBUG-PROBE/N56797: IC2.F1(USB0_ID) R28.2
LPC-LINK2-DEBUG-PROBE/N66019: IC18.12(B) R37.1
LPC-LINK2-DEBUG-PROBE/N66978: IC18.2(DIR) IC18.7(DIR) IC18.15(DIR) IC24.2(DIR) R54.1 R65.2
LPC-LINK2-DEBUG-PROBE/N68312: IC18.9(~{OE}) IC24.9(~{OE}) JP6.2 R40.2
LPC-LINK2-DEBUG-PROBE/N71636: C29.1 IC19.4(IN2) IC20.1(Z) Z2.1
LPC-LINK2-DEBUG-PROBE/N72134: C30.1 IC19.5(IN1) IC21.3(OUT)
LPC-LINK2-DEBUG-PROBE/N73560: IC20.7(Y0) JS9.2
LPC-LINK2-DEBUG-PROBE/N73566: IC20.6(Y1) JS10.2
LPC-LINK2-DEBUG-PROBE/N73572: JS9.1 Z8.1
LPC-LINK2-DEBUG-PROBE/N74112: IC21.5(RS+) JS5.2
LPC-LINK2-DEBUG-PROBE/N74501: IC21.4(RS-) JS6.2
LPC-LINK2-DEBUG-PROBE/N79459: R56.1 SW4.A SW4.AP
LPC-LINK2-DEBUG-PROBE/N89420: JS7.2 R62.1
LPC-LINK2-DEBUG-PROBE/N89424: JS8.2 R48.1
LPC-LINK2-DEBUG-PROBE/N122096: R31.1 SW2.A SW2.AP
LPC-LINK2-DEBUG-PROBE/N141189: DS5.K IC13.3(A) R68.2
LPC-LINK2-DEBUG-PROBE/N207700: DS6.A R82.2
LPC-LINK2-DEBUG-PROBE/N266494: IC22.1(TXD) R2.2
LPC-LINK2-DEBUG-PROBE/N266498: IC22.2(~{RTS}) R8.2
LPC-LINK2-DEBUG-PROBE/N266506: IC22.4(RXD) R98.2
LPC-LINK2-DEBUG-PROBE/N266526: IC22.6(~{CTS}) R44.2
LPC-LINK2-DEBUG-PROBE/N266530: D3.3(CATHODE) IC22.7(CBUS2)
LPC-LINK2-DEBUG-PROBE/N266542: D5.3(CATHODE) IC22.16(CBUS3)
LPC-LINK2-DEBUG-PROBE/N266566: C36.1 IC22.8(USBDP) J2.3(D+)
LPC-LINK2-DEBUG-PROBE/N266586: C35.1 IC22.9(USBDM) J2.2(D-)
LPC-LINK2-DEBUG-PROBE/N266606: C34.1 FE3.1 J2.1(VCC)
LPC-LINK2-DEBUG-PROBE/N271511: DS4.A R57.2
LPC-LINK2-DEBUG-PROBE/N271644: DS8.A R84.2
N302589: IC18.5(A) R38.2
N312462: D1.A R20.1
N312465: DS5.A R81.2
POWER-SUPPLY/N250681: C23.1 C24.1 D2.4 FE1.2 J15.1(VCC)
POWER-SUPPLY/N16933640: J7.1 J7.2 J13.3 J13.4
POWER-SUPPLY/N16933832: C6.1(P) IC5.1(VIN) IC5.3(ON/OFF) JP3.2
POWER-SUPPLY/N16933939: C38.1 IC5.4(NOISE)
POWER-SUPPLY/N16935646: DS1.K R83.1
POWER-SUPPLY/N16937171: C43.1 IC1.5(VOUT) JS3.1
POWER-SUPPLY/N16960585: D4.1(ANODE) J4.1
USER INTERFACES MEMORY/N00514: IC4.3(SCL) R43.1 R45.1
USER INTERFACES MEMORY/N00856: IC4.5(SDA) R42.1 R59.1
USER INTERFACES MEMORY/N51116: C16.2 IC4.8(LB) R50.2 TP5.1
USER INTERFACES MEMORY/N51152: ANT2.1 ANT2.2 R32.1 R49.1 R50.1 R58.2
USER INTERFACES MEMORY/N51176: C16.1 IC4.1(LA) R49.2 TP6.1
USER INTERFACES MEMORY/N52248: IC4.7(VOUT) R41.1 R67.2 TP1.1
USER INTERFACES MEMORY/N54003: DS3.A R46.2
USER INTERFACES MEMORY/N54147: DS2.A R64.2
USER INTERFACES MEMORY/N66353: D7.A R67.1

Not connected (* = marked no-connect by the designer): 1 1*; 8D_X9 1*; CN3 1*; IC1 4(NC)*; IC2 A1(ADC1)* A3(ADC3)* A5(RTCX1)* A8(P3[0]_/I2S0_RX_SCK/I2S0_RX_MCLK/I2S0_TX_SCK/I2S0_TX_MCLK)* B3(ADC2)* B5(RTCX2)* B7(P3[5]_/GPIO1[15]///SPIFI_SIO2)* B8(P3[4]_/GPIO1[14]///SPIFI_SIO3)* B9(P2[12]_/GPIO1[12]/CTOUT_4/NC/EXTBUS_A3)* C3(RTC_ALARM)* D8(P2[3]_/SGPIO12/I2C1_SDA/U3_TXD/CTIN_1)* D9(P2[4]_/SGPIO13/I2C1_SCL/U3_RXD/CTIN_0)* E8(P2[10]_/GPIO0[14]/CTOUT_2/U2_TXD/EXTBUS_A1)* E9(USB1_DP)* E10(USB1_DM)* F6(P6[4]_/GPIO3[3]/CTIN_6/U0_TXD/EXTBUS_nCAS)* F7(P3[1]_/I2S0_TX_WS/I2S0_RX_WS/CAN0_RD/USB1_IND1/GPIO5[8])* G1(P0[1]_/GPIO0[1]/SSP1_MOSI/ENET_TXEN/SGPIO1)* G2(P0[0]_/GPIO0[0]/SSP1_MISO/ENET_RXD1/SGPIO0)* G3(STDI/TDI)* G4(P1[7]_/GPIO1[0]/U1_DSR/CTOUT_13/EXTBUS_D0)* G5(P6[1]_/GPIO3[0]/EXTBUS_nDYCS1/U0_UCLK/I2S0_RX_WS)* G6(P3[2]_/I2S0_TX_SDA/I2S0_RX_SDA/CAN0_TD/USB1_IND0/GPIO5[9])* H3(TDO/SWO)* H4(PF[4]_/SSP1_SCK/SPIFI_CLKIN/TRACECLK///I2S_TX_MCLK/I2S_RX_MCLK)* H5(P1[8]_/GPIO1[1]/U1_DTR/CTOUT_12/EXTBUS_D1)* H6(P1[10]_/GPIO1[3]/U1_RI/CTOUT_14/EXTBUS_D3)* H7(P6[0]_/I2S0_RX_MCLK///I2S0_RX_SCK)* H8(P1[13]_/GPIO1[6]/U1_TXD/NC/EXTBUS_D6)* H9(P1[16]_/GPIO0[3]/U2_RXD/SGPIO3/ENET_RX_DV)* K3(CLK0_/EXTBUS_CLK0/CLKOUT)* K6(CLK2_/EXTBUS_CLK2/CLKOUT//SDIO_CLK/I2S0_TX_MCLK/I2S1_RX_CLK)* K7(P1[12]_/GPIO1[5]/U1_DCD/NC/EXTBUS_D5)* K8(P1[15]_/GPIO0[2]/U2_TXD/SGPIO2/ENET_RXD0)*; IC10 1(NC)*; IC11 13(Y0)* 16(Z)*; IC22 14(CBUS1)* 15(CBUS0)*; J2 4(OTG_ID)*; J14 3*; JM1 4* 11* 13*; JM2 6* 8* 10* 12* 15* 17* 19*; JP1 3*; JP2 3*; JP5 3*; JP6 3*; M6 1*

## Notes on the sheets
sheet 1
- JN5189 CARRIER MAIN BOARD
  DK6 V3 OM15076-3
- POWER
- USB
- I2C
- SWD
- SPI
- UART
- ISP
- IF
- NFC
- SPI
- MEMORY
- Antenna Holes
- Asco: PCB2455-3-200-00
sheet 2
- LPC-LINK2-DEBUG-PROBE 1/3
- NC
- NC
- NC
- NC
- NC
- NC
- NC
- NC
- NC
- NC
- NC
- NC
sheet 3
- LPC-LINK2-DEBUG-PROBE 2/3
- NC
- NC
- NC
- NC
- NC
- NC
- NC
- NC
- NC
- NC
- NC
- NC
- NC
- NC
- TRACE_CLK
- NC
- NC
- NC
- LINK  LPC4322 BOOT MODE
- TRACE_D2
- NC
- TRACE_D3
- NC
- DFU USB0= B3:0
          = 0101
- BUFFER PWR SELECT
  ON (1-2): LOCAL TARGET (Default)
  OFF(2-3): EXTERNAL TARGET
- NC
- NC
- JP5(1-2) to force DFU boot (Default)
  (when internal flash is programmed)
  JP5(2-3) Normal Mode.
- Option : External Target.
- NC
- TARGET SWD DEBUG: ON(2-3),OFF(1-2)
sheet 4
- LPC-LINK2-DEBUG-PROBE 3/3
- VOLTAGE GAIN 25V/V
- JN518X CURRENT MEASUREMEN
- UART TO FTDI USB
- (JN5189_PIO9)
- (JN5189_PIO7)
- (JN5189_PIO8)
- ISP BOOTLOAD ENABLE
- RESET
- ENABLE->
- OPTION To
  Connect USART1
- OPTION To
  Connect USART1
- USART0
  to LPC
  or FTDI
- USART0
  to LPC
  or FTDI
sheet 5
- POWER SUPPLY
- USB CONNECTOR
- LPC LINK2 SUPPLY
- Power Supply
- CURRENT SENSE SELECT(J14)
  SENSE DISABLED 1-2 (default)
  SENSE ENABLES 2-3
- 3V3
- 5V REG
- VIN
- 3V3REG
- (To Module Connectors)
- BAT 6V
- LDO 3V3
- LDO 5V
- BAT 3V
- PWR LED
- Battery Clips
sheet 6
- USER INTERFACES MEMORY
- NFC
- NTAG
- USER BUTTON AND LEDS
- QSPI FLASH MEMORY
sheet 7
- CONNECTORS
- ARDUINO CONNECTORS
- Module Connections
- (PIO_8/USART0_TXD)
- (PIO_9/USART0_RXD)
- EXPANSION HEADER 34 PINS
- DIGITAL
- 10
- 9
- 8
- 7
- 6
- 5
- 4
- 3
- 2
- 1
- 8
- 7
- 6
- 5
- 4
- 3
- 2
- 1
- GND
- VDD_TRGT
- RSTN
- 3V3
- GND
- GND
- VIN
- ANALOG IN
- NC
- 5V
- A
- B
- C
- D
- E
- F
- Analog
  Comparator
- POWER
- Option : Bridge Resistors To Isolate QSPI.
- ADC
